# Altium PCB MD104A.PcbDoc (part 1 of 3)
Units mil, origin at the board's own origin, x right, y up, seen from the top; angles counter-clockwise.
Board outline 3684 x 4279 mil, 4 copper layers (Top Layer, GND Layer, Power Layer, Bottom Layer), stack 61.2 mil thick; 215 components, 107 nets, 500 pads, 726 vias.
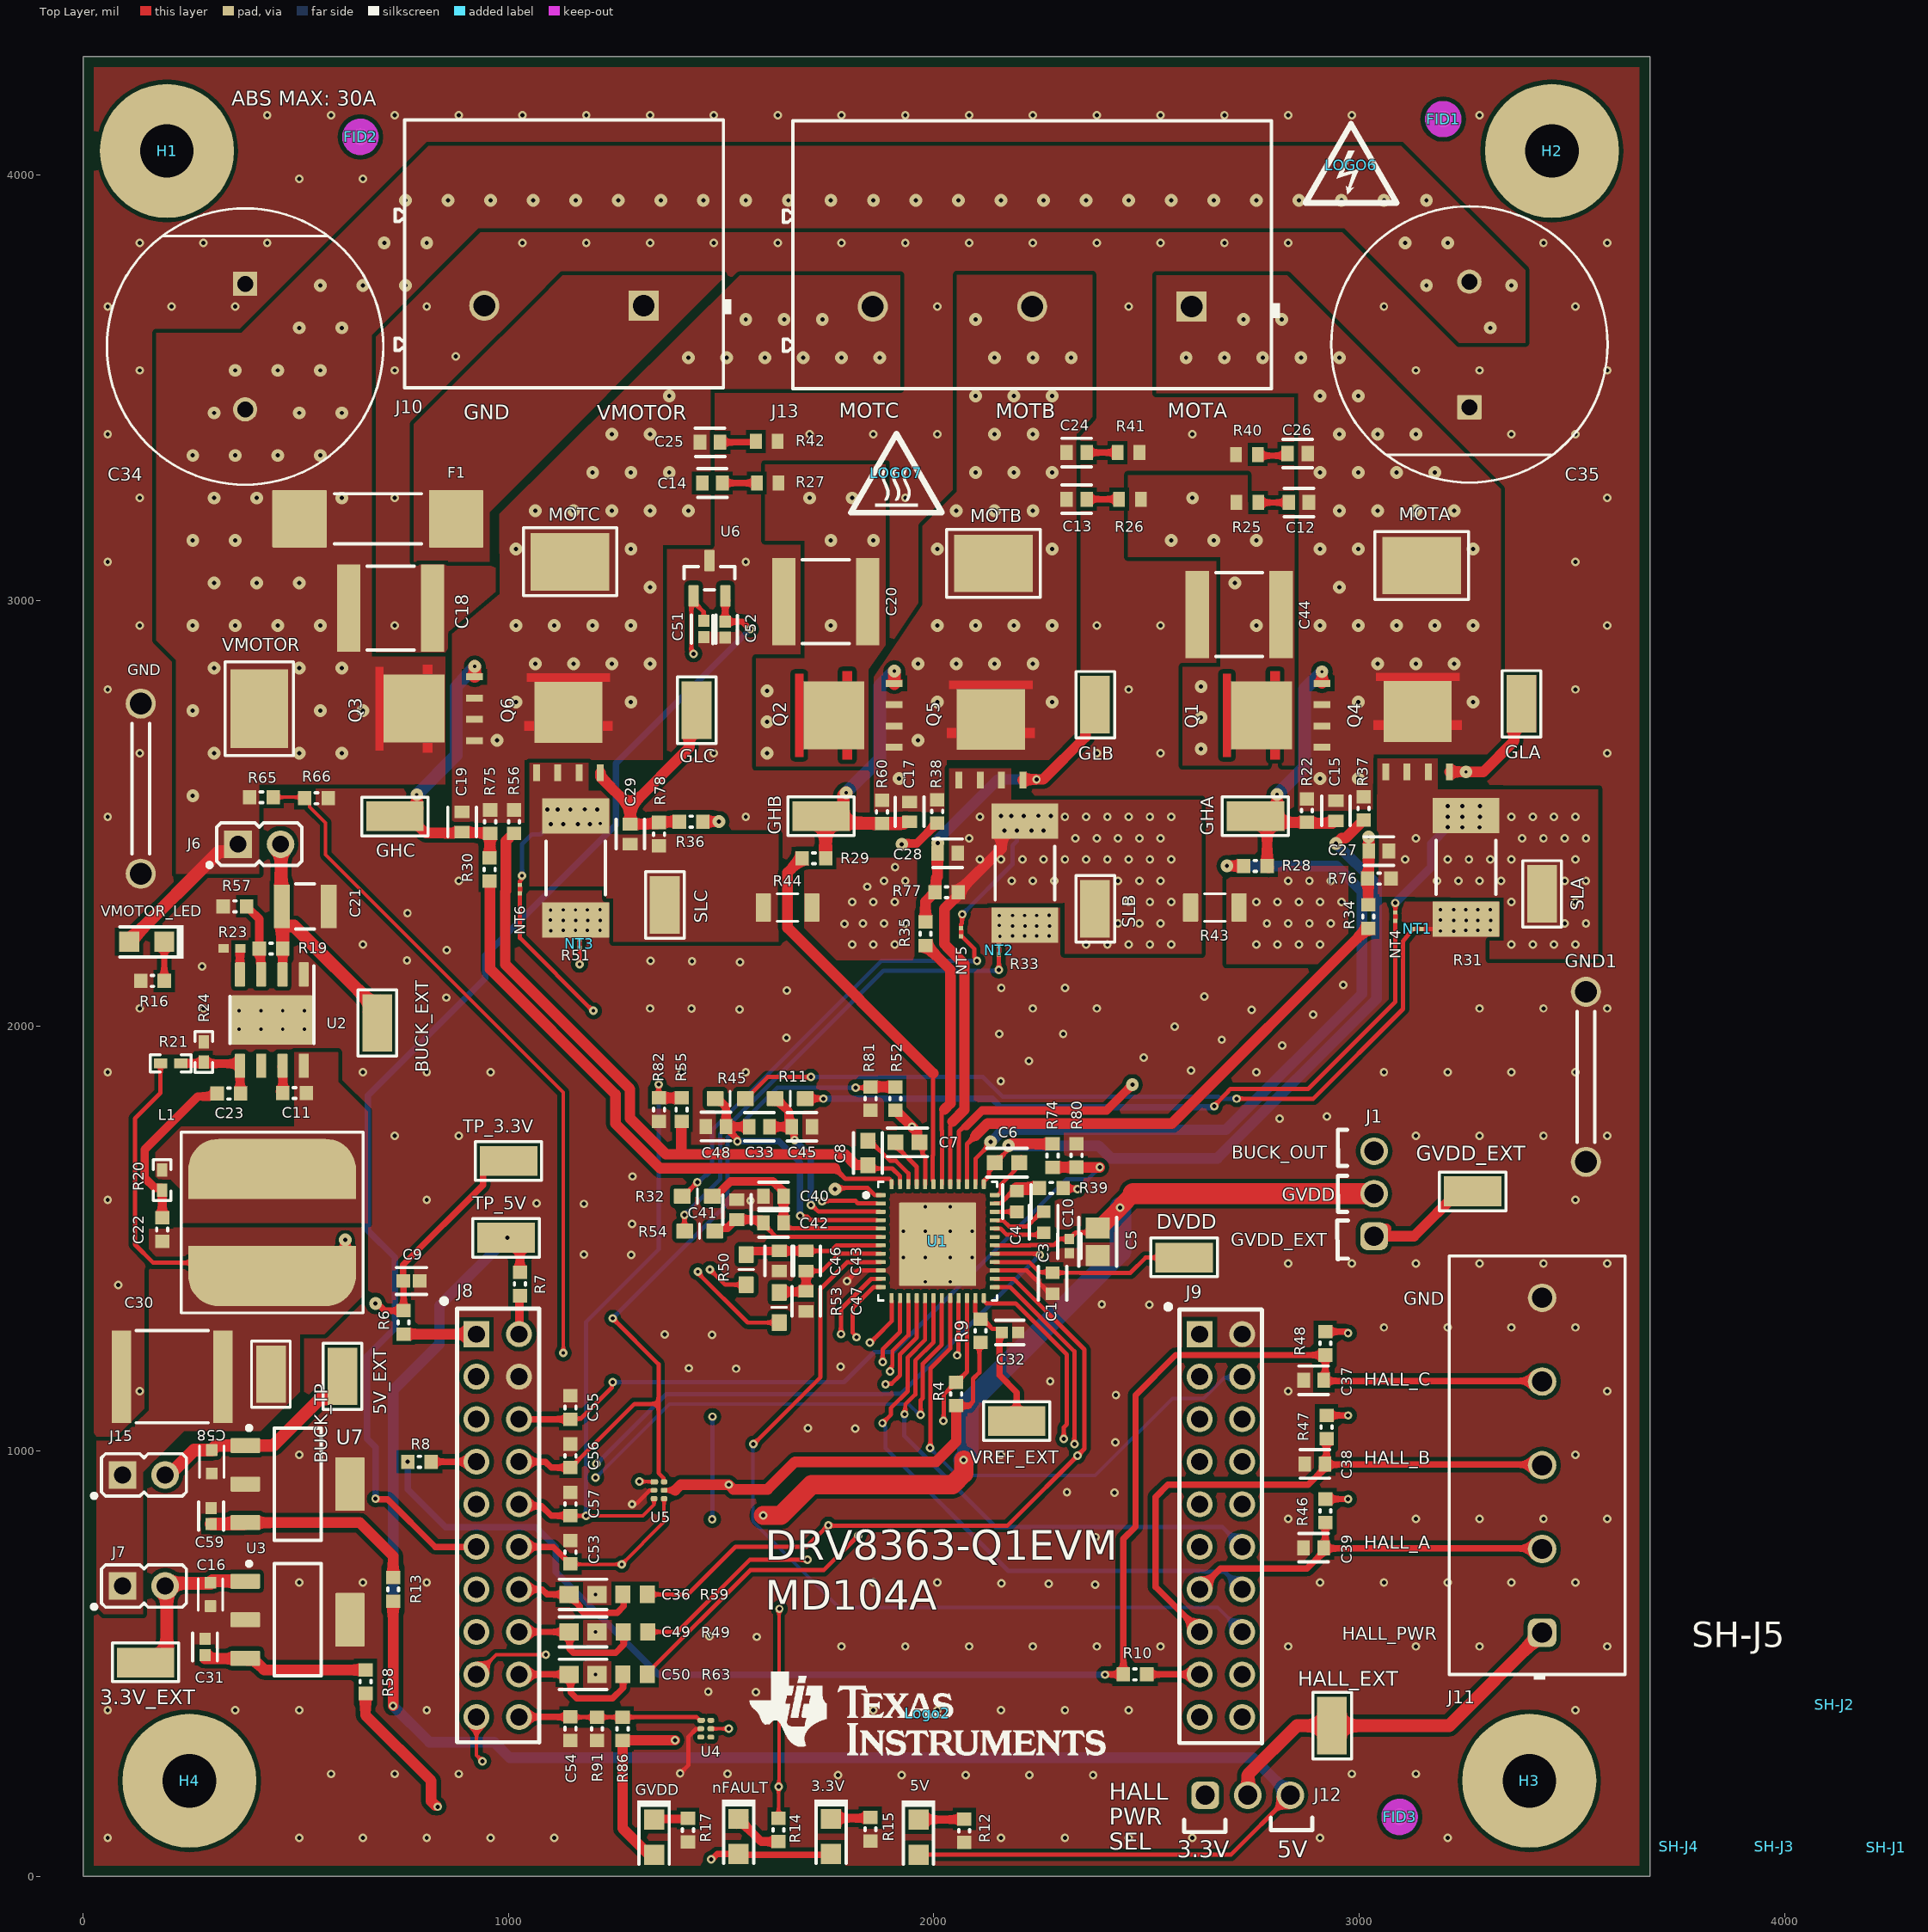
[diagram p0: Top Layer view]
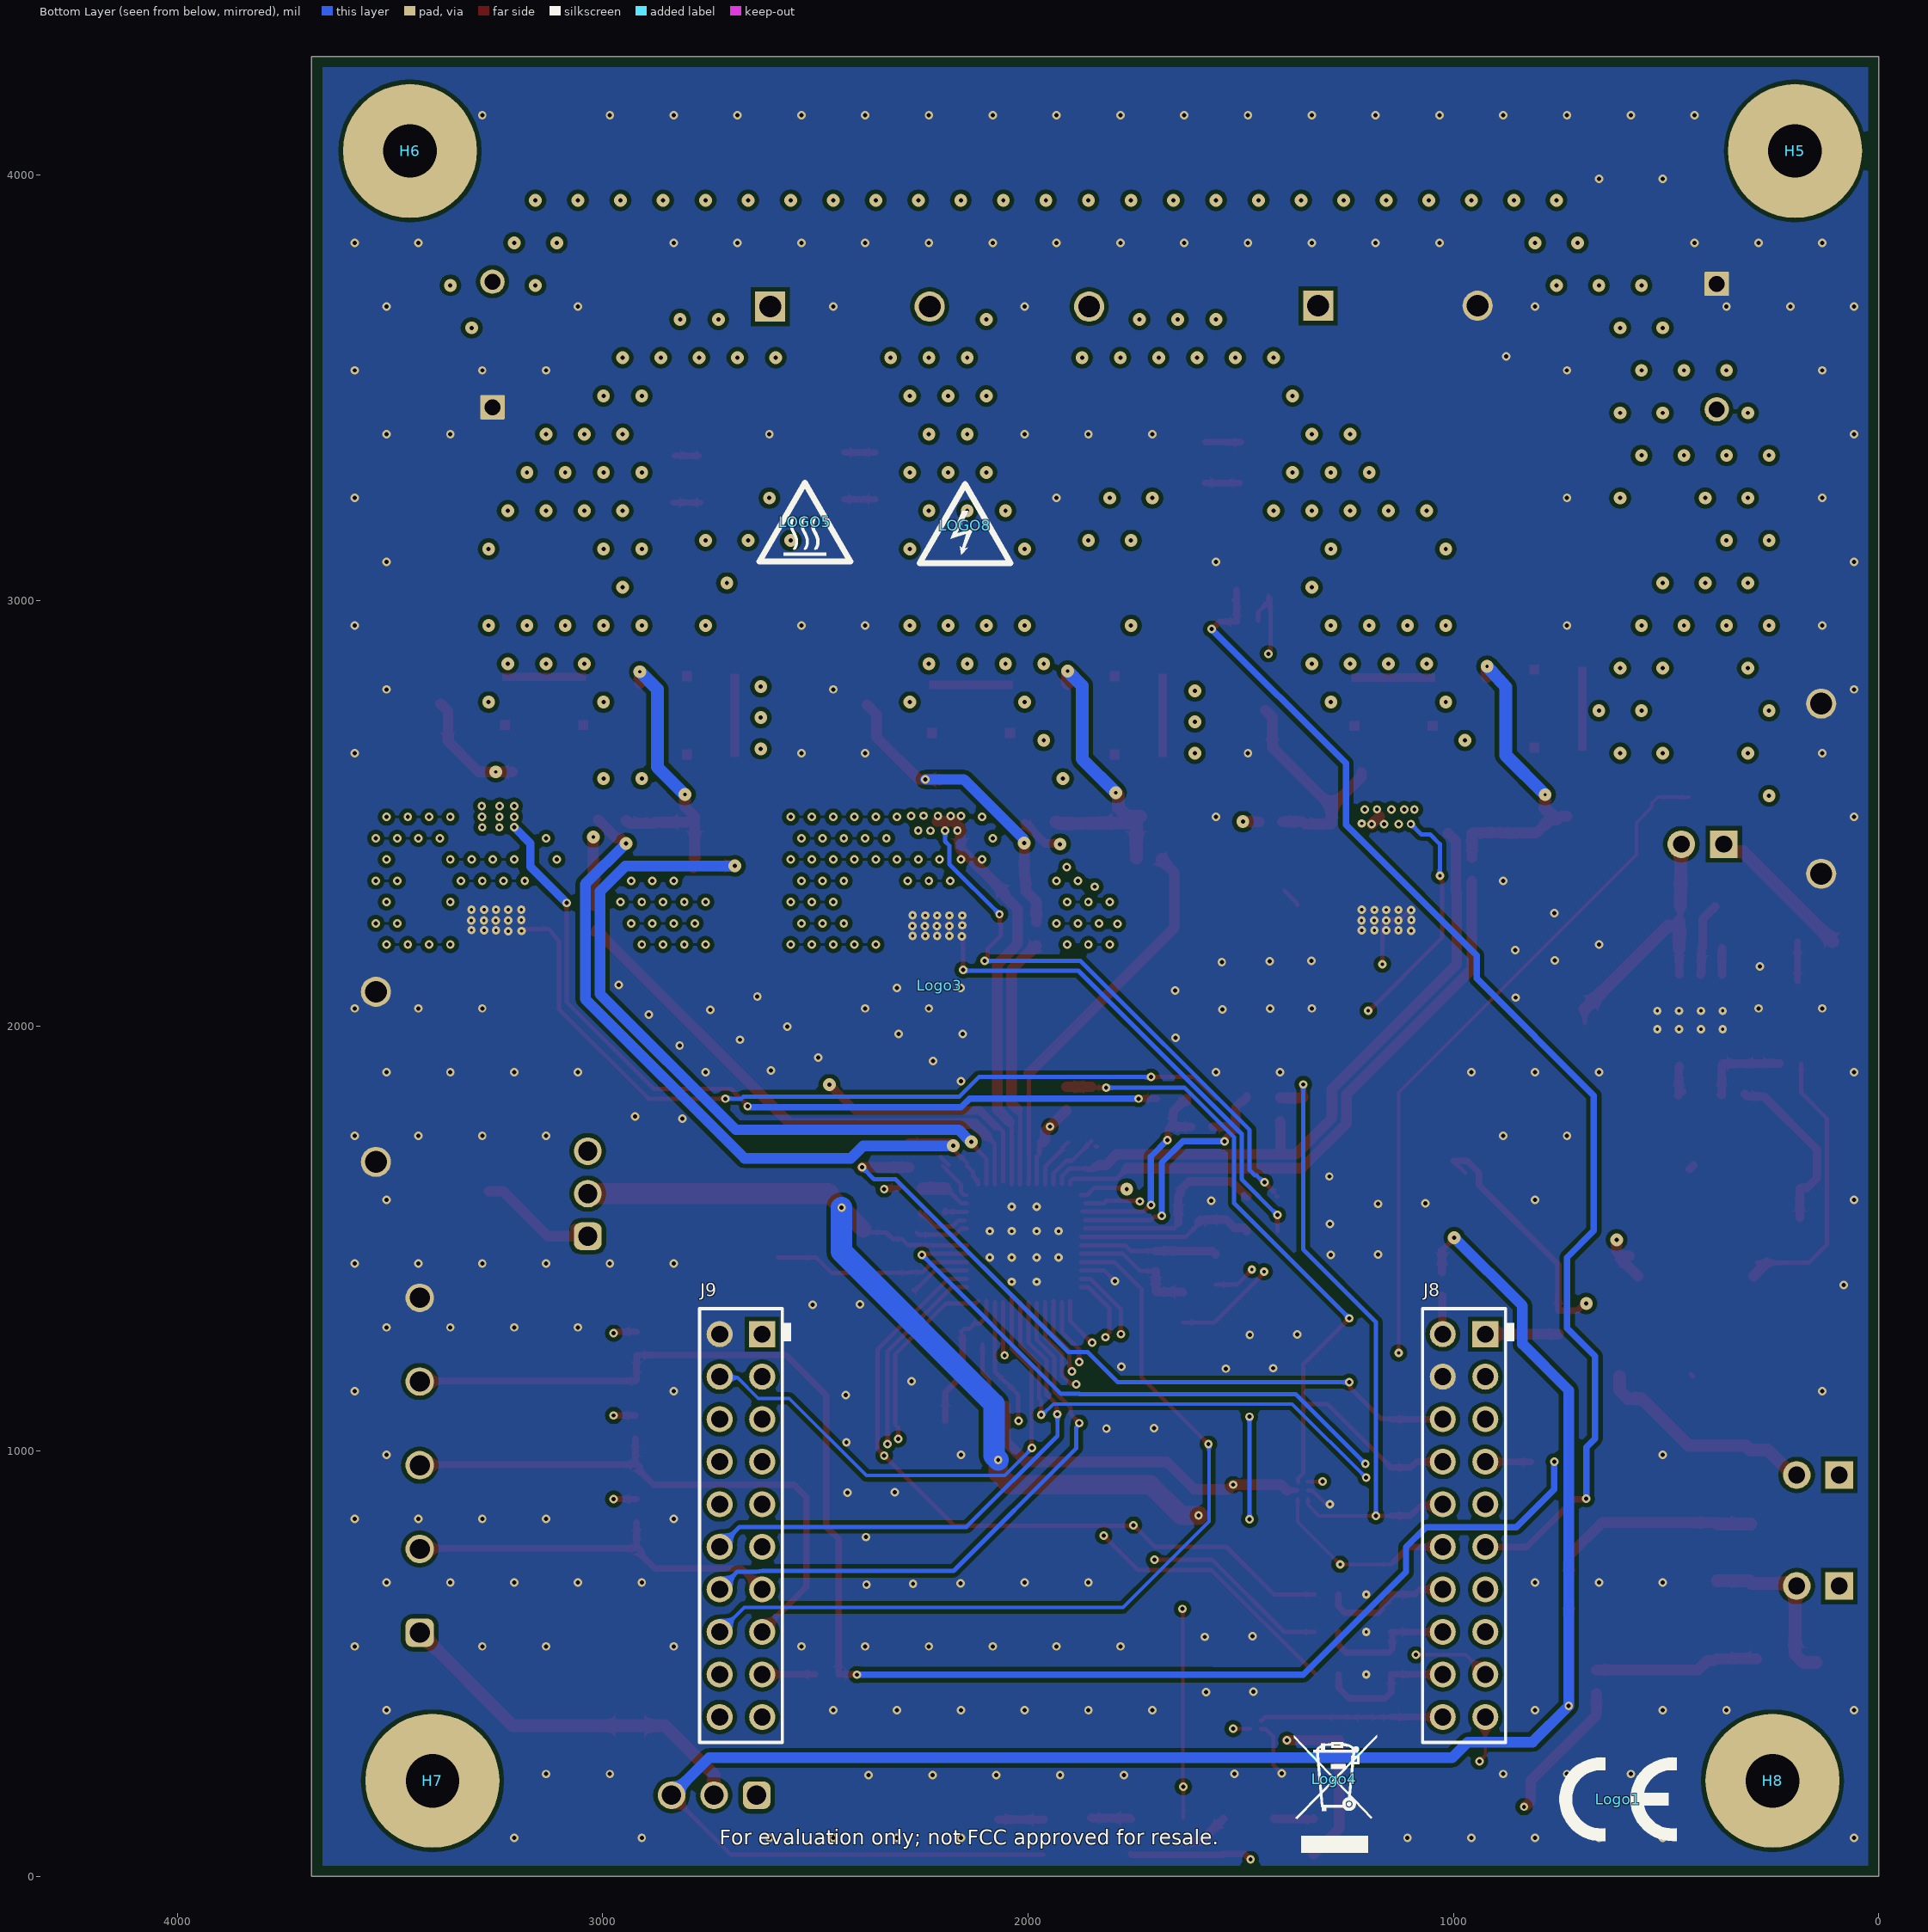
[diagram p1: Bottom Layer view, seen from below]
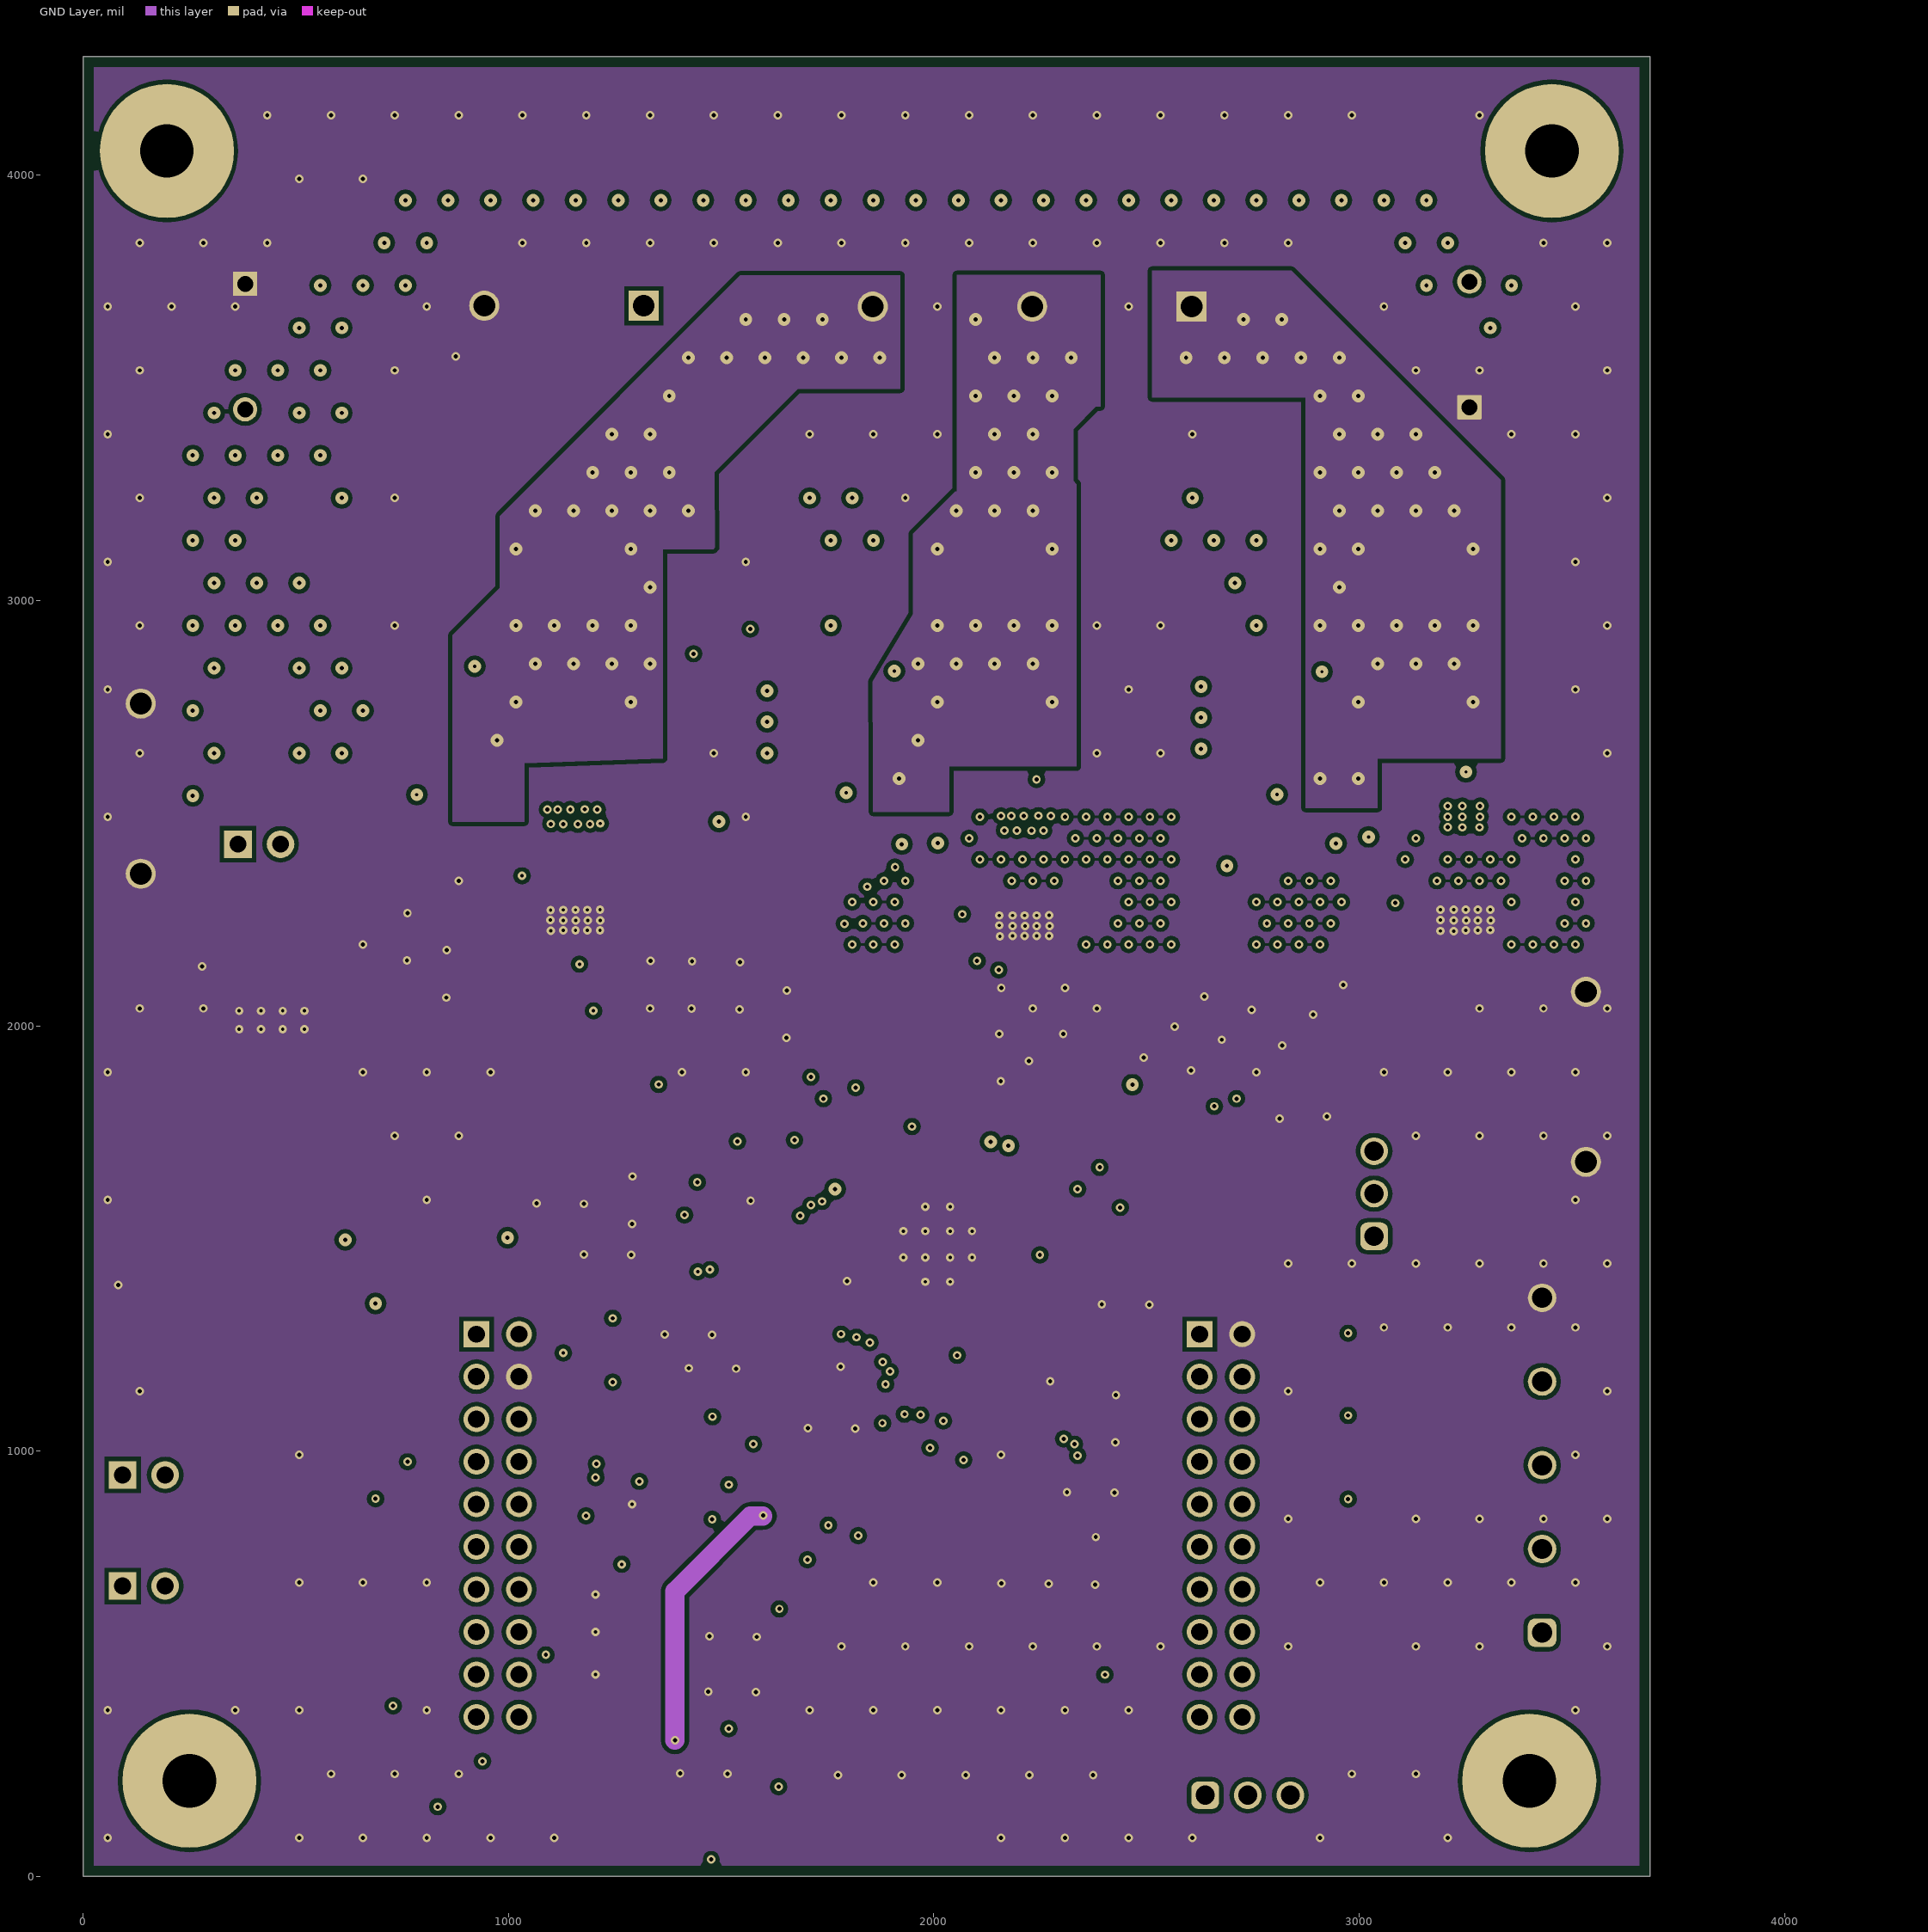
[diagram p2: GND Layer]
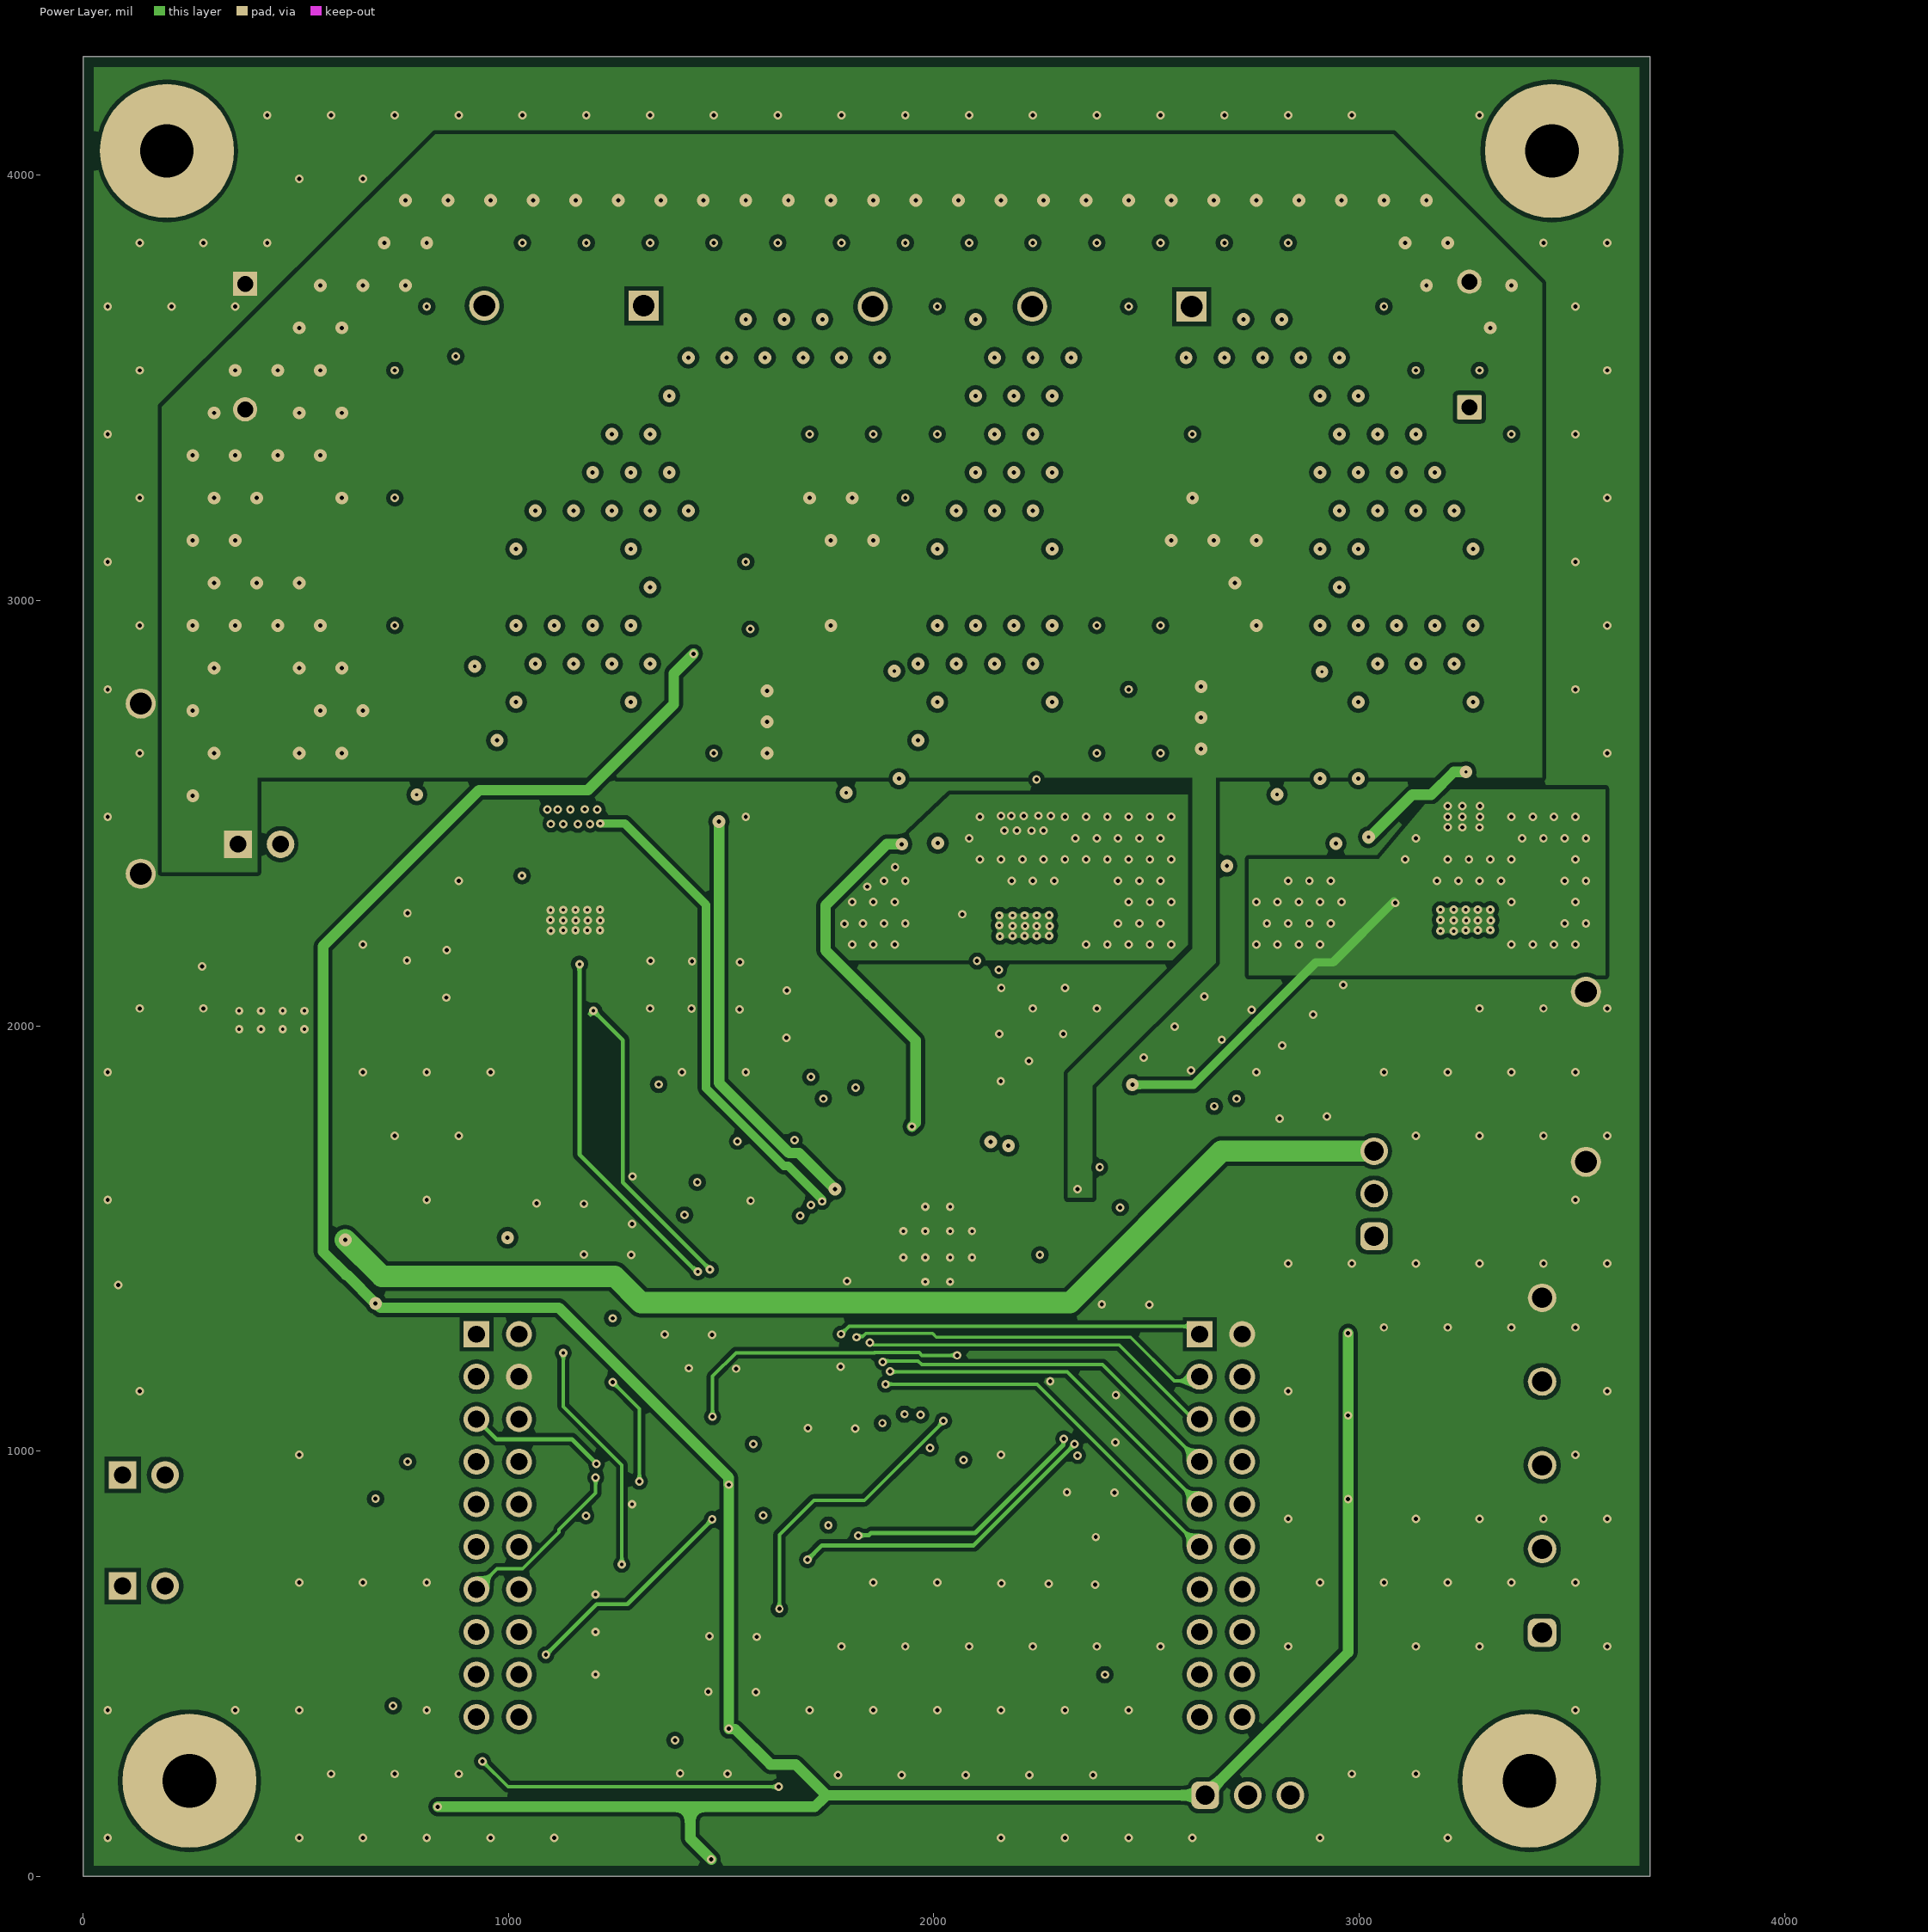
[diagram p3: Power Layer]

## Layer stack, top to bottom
Top Solder: solder mask 0.4, Solder Resist, Dk 3.5
Top Layer: signal copper 2.8
Dielectric 2: core 10, FR-4 High Tg, Dk 4.8
GND Layer: signal copper 1.4
Dielectric 1: prepreg 32.8, FR-4 High Tg, Dk 4.2
Power Layer: signal copper 1.4
Dielectric 3: core 10, FR-4 High Tg, Dk 4.8
Bottom Layer: signal copper 2.8
Solder Side: solder mask 0.4, Solder Resist, Dk 3.5

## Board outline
0,0 3684,0 3684,4279 0,4279

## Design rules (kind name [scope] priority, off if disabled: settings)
AcuteAngle [All] p1: minimum=4.50000000000000E+0001 checktracksonly=FALSE
AssemblyTestPointUsage [All] p1: valid=2
BoardOutlineClearance BoardOutlineClearance_MountingHoles [OnCopper and InComponentClass('Mounting Holes')] p1: gap=39.37 ignorepadtopadclearanceinfootprint=FALSE
BoardOutlineClearance BoardOutlineClearance_Poly [OnCopper and IsPoly] p2: gap=25 ignorepadtopadclearanceinfootprint=FALSE
BoardOutlineClearance [OnCopper and Not InComponentClass('Logo') and not InComponentClass('FiducialMark') and not InRegion(1000,500,4000,800) and not InPoly] p3: gap=50 ignorepadtopadclearanceinfootprint=FALSE
Clearance Clearance_Keepouts [((IsTrack Or IsArc) And Not InPoly) And IsFree and IsKeepOut vs ((IsTrack Or IsArc) And Not InPoly) And IsFree and IsKeepOut] p1: gap=0 ignorepadtopadclearanceinfootprint=FALSE
Clearance Clearance_Poly [InPolygon] p2: gap=10 ignorepadtopadclearanceinfootprint=TRUE
Clearance Clearance_FiducialMark [IsKeepOut and InComponentClass('FiducialMark') vs IsPad and InComponentClass('FiducialMark')] p3: gap=0 ignorepadtopadclearanceinfootprint=FALSE
Clearance [All] p4: gap=7.87 ignorepadtopadclearanceinfootprint=TRUE
ComponentClearance ComponentClearance_MountingHoles_FiducialMarks [InComponentClass('Mounting Holes') vs InComponentClass('FiducialMark')] p1: gap=50 collisioncheckmode=3 verticalgap=10 showdistances=FALSE
ComponentClearance ComponentClearance_Shunt [InComponentClass('Header') vs InComponentClass('Shunt')] p2: gap=0 collisioncheckmode=3 verticalgap=0 showdistances=FALSE
ComponentClearance ComponentClearance_Logo [InComponentClass('Logo')] p3: gap=20 collisioncheckmode=3 verticalgap=10 showdistances=FALSE
ComponentClearance ComponentClearance_ScrewToNut [(HasFootprint('NY PMS 440 0025 PH')) vs (HasFootprint('Keystone_1902C'))] p4: gap=5 collisioncheckmode=3 verticalgap=10 showdistances=FALSE
ComponentClearance ComponentClearance_MountingHoles [InComponentClass('Mounting Holes')] p5: gap=10 collisioncheckmode=3 verticalgap=100000 showdistances=FALSE
ComponentClearance ComponentClearance_SmallPassives [HasFootprint('0201*') or HasFootprint('0402*') or HasFootprint('0508') or HasFootprint('0603*') or HasFootprint('0612') or HasFootprint('0805*') or HasFootprint('0815*') or HasFootprint('0830*') or HasFootprint('1206*') or HasFootprint('1210*') or HasFootprint('1808*') or HasFootprint('1812*') or HasFootprint('1825*') or HasFootprint('2010*') or HasFootprint('2220*') or HasFootprint('2225*') or HasFootprint('2512*') or HasFootprint('2728*') or HasFootprint('3518*') vs HasFootprint('0201*') or HasFootprint('0402*') or HasFootprint('0508') or HasFootprint('0603*') or HasFootprint('0612') or HasFootprint('0805*') or HasFootprint('0815*') or HasFootprint('0830*') or HasFootprint('1206*') or HasFootprint('1210*') or HasFootprint('1808*') or HasFootprint('1812*') or HasFootprint('1825*') or HasFootprint('2010*') or HasFootprint('2220*') or HasFootprint('2225*') or HasFootprint('2512*') or HasFootprint('2728*') or HasFootprint('3518*')] p6: gap=14.96 collisioncheckmode=3 verticalgap=10 showdistances=FALSE
ComponentClearance ComponentClearance_THtoSMT [IsThruComponent vs IsSMTComponent] p7: gap=40 collisioncheckmode=3 verticalgap=30 showdistances=FALSE
ComponentClearance ComponentClearance_THtoTH [IsThruComponent vs IsThruComponent] p8: gap=30 collisioncheckmode=3 verticalgap=30 showdistances=FALSE
ComponentClearance [All] p9: gap=30 collisioncheckmode=3 verticalgap=10 showdistances=FALSE
DiffPairsRouting [All] p1: maxlimit=100 minlimit=10 mostfreqgap=10 toplayer_minwidth=15 toplayer_maxwidth=15 toplayer_prefwidth=15 midlayer1_minwidth=15 midlayer1_maxwidth=15 midlayer1_prefwidth=15 midlayer2_minwidth=15 midlayer2_maxwidth=15 midlayer2_prefwidth=15 bottomlayer_minwidth=15 bottomlayer_maxwidth=15 bottomlayer_prefwidth=15 maxuncoupledlength=1000
FabricationTestPointUsage TestPointUsage [All] p1: valid=2 allowmultiple=FALSE
FabricationTestpoint Testpoint [All] p1: side=3 testpointundercomponent=TRUE minsize=40 maxsize=100 preferedsize=60 minholesize=0 maxholesize=40 preferedholesize=32 testpointgrid=1 allowsidetop=TRUE allowsidebottom=TRUE usegrid=TRUE gridtolerance=0.01
FanoutControl Fanout_LCC [IsLCC] p1: bgadir=Out bgaviamode=Centered fanoutstyle=Auto fanoutdirection=Alternating viagrid=1 // Fanout_LCC (Default Rule)
FanoutControl Fanout_BGA [IsBGA] p2: bgadir=Out bgaviamode=Centered fanoutstyle=Auto fanoutdirection=Alternating viagrid=1 // Fanout_BGA (Default Rule)
FanoutControl Fanout_Default [All] p4: bgadir=Out bgaviamode=Centered fanoutstyle=Auto fanoutdirection=Alternating viagrid=1 // Fanout_Default (Default Rule)
FanoutControl Fanout_Small [(CompPinCount < 5)] p5: bgadir=Out bgaviamode=Centered fanoutstyle=Auto fanoutdirection=OutThenIn viagrid=1 // Fanout_Small (Default Rule)
Height [All] p1 off: minheight=0 maxheight=1000 prefheight=500
HoleSize [All] p1: absolutevalues=TRUE maxlimit=250 minlimit=7.8 maxpercent=80.000 minpercent=20.000
MinimumAnnularRing MinimumAnnularRing_ThermalPadVias [IsVia and InAnyComponent] p1: minimumring=5
MinimumAnnularRing [All] p2: minimumring=5
MinimumSolderMaskSliver MinimumSolderMaskSliver_Logo [InComponentClass('Logo') vs InComponentClass('Logo')] p1: minsoldermaskwidth=0.7
MinimumSolderMaskSliver [All] p2: minsoldermaskwidth=3.94
PlaneConnect [All] p1: planeconnectstyle=Direct reliefexpansion=10 reliefentries=4 reliefconductorwidth=10 reliefairgap=10
PolygonConnect PolygonConnect_57 [All] p1: connectstyle=Direct reliefconductorwidth=10 reliefentries=4 polygonreliefangle="90 Angle" airgapwidth=10
PolygonConnect PolygonConnect_56 [All vs IsNamedPolygon('Top Layer-MOTB')] p2: connectstyle=Direct reliefconductorwidth=10 reliefentries=4 polygonreliefangle="90 Angle" airgapwidth=10
PolygonConnect PolygonConnect_55 [All vs IsNamedPolygon('TOP_LAYER_SLB_P107')] p3: connectstyle=Direct reliefconductorwidth=10 reliefentries=4 polygonreliefangle="90 Angle" airgapwidth=10
PolygonConnect PolygonConnect_54 [All vs IsNamedPolygon('TOP_LAYER_SLC_P118')] p4: connectstyle=Direct reliefconductorwidth=10 reliefentries=4 polygonreliefangle="90 Angle" airgapwidth=10
PolygonConnect PolygonConnect_53 [All vs IsNamedPolygon('TOP_LAYER_SLC_P118')] p5: connectstyle=Direct reliefconductorwidth=10 reliefentries=4 polygonreliefangle="90 Angle" airgapwidth=10
PolygonConnect PolygonConnect_52 [All vs IsNamedPolygon('TOP_LAYER_SLB_P113')] p6: connectstyle=Direct reliefconductorwidth=10 reliefentries=4 polygonreliefangle="90 Angle" airgapwidth=10
PolygonConnect [All vs IsNamedPolygon('TOP_LAYER_SLA_P109')] p7: connectstyle=Direct reliefconductorwidth=10 reliefentries=4 polygonreliefangle="90 Angle" airgapwidth=10
PolygonConnect PolygonConnect_51 [All vs IsNamedPolygon('TOP_LAYER_NONET_P084')] p8: connectstyle=Direct reliefconductorwidth=10 reliefentries=4 polygonreliefangle="90 Angle" airgapwidth=10
PolygonConnect PolygonConnect_50 [All vs IsNamedPolygon('BOTTOM_LAYER_GND_P082')] p9: connectstyle=Direct reliefconductorwidth=10 reliefentries=4 polygonreliefangle="90 Angle" airgapwidth=10
PolygonConnect PolygonConnect_49 [All vs IsNamedPolygon('GND_LAYER_LSS_P072')] p10: connectstyle=Direct reliefconductorwidth=10 reliefentries=4 polygonreliefangle="90 Angle" airgapwidth=10
PolygonConnect PolygonConnect_48 [All vs IsNamedPolygon('POWER_LAYER_LSS_P076')] p11: connectstyle=Direct reliefconductorwidth=10 reliefentries=4 polygonreliefangle="90 Angle" airgapwidth=10
PolygonConnect PolygonConnect_47 [All vs IsNamedPolygon('GND_LAYER_LSS_P072')] p12: connectstyle=Direct reliefconductorwidth=10 reliefentries=4 polygonreliefangle="90 Angle" airgapwidth=10
PolygonConnect PolygonConnect_46 [All vs IsNamedPolygon('BOTTOM_LAYER_GND_P076')] p13: connectstyle=Direct reliefconductorwidth=10 reliefentries=4 polygonreliefangle="90 Angle" airgapwidth=10
PolygonConnect PolygonConnect_45 [All vs IsNamedPolygon('BOTTOM_LAYER_OUTA_P076')] p14: connectstyle=Direct reliefconductorwidth=10 reliefentries=4 polygonreliefangle="90 Angle" airgapwidth=10
PolygonConnect PolygonConnect_44 [All vs IsNamedPolygon('BOTTOM_LAYER_OUTB_P074')] p15: connectstyle=Direct reliefconductorwidth=10 reliefentries=4 polygonreliefangle="90 Angle" airgapwidth=10
PolygonConnect PolygonConnect_43 [All vs IsNamedPolygon('BOTTOM_LAYER_OUTC_P072')] p16: connectstyle=Direct reliefconductorwidth=10 reliefentries=4 polygonreliefangle="90 Angle" airgapwidth=10
PolygonConnect PolygonConnect_42 [All vs IsNamedPolygon('BOTTOM_LAYER_NONET_P070')] p17: connectstyle=Direct reliefconductorwidth=10 reliefentries=4 polygonreliefangle="90 Angle" airgapwidth=10
PolygonConnect PolygonConnect_41 [All vs IsNamedPolygon('POWER_LAYER_GND_P068')] p18: connectstyle=Direct reliefconductorwidth=10 reliefentries=4 polygonreliefangle="90 Angle" airgapwidth=10
PolygonConnect PolygonConnect_40 [All vs IsNamedPolygon('GND_LAYER_GND_P066')] p19: connectstyle=Direct reliefconductorwidth=10 reliefentries=4 polygonreliefangle="90 Angle" airgapwidth=10
PolygonConnect PolygonConnect_39 [All vs IsNamedPolygon('TOP_LAYER_GND_P070')] p20: connectstyle=Direct reliefconductorwidth=10 reliefentries=4 polygonreliefangle="90 Angle" airgapwidth=10
PolygonConnect PolygonConnect_38 [All vs IsNamedPolygon('BOTTOM_LAYER_GND')] p21: connectstyle=Direct reliefconductorwidth=10 reliefentries=4 polygonreliefangle="90 Angle" airgapwidth=10
PolygonConnect PolygonConnect_37 [All vs IsNamedPolygon('BOTTOM_LAYER_GND')] p22: connectstyle=Direct reliefconductorwidth=10 reliefentries=4 polygonreliefangle="90 Angle" airgapwidth=10
PolygonConnect PolygonConnect_36 [All vs IsNamedPolygon('GND_LAYER_OUTA_P060')] p23: connectstyle=Direct reliefconductorwidth=10 reliefentries=4 polygonreliefangle="90 Angle" airgapwidth=10
PolygonConnect PolygonConnect_35 [All vs IsNamedPolygon('GND_LAYER_OUTB_P058')] p24: connectstyle=Direct reliefconductorwidth=10 reliefentries=4 polygonreliefangle="90 Angle" airgapwidth=10
PolygonConnect PolygonConnect_34 [All vs IsNamedPolygon('GND_LAYER_OUTC_P056')] p25: connectstyle=Direct reliefconductorwidth=10 reliefentries=4 polygonreliefangle="90 Angle" airgapwidth=10
PolygonConnect PolygonConnect_33 [All vs IsNamedPolygon('POWER_LAYER_PVDD_P052')] p26: connectstyle=Direct reliefconductorwidth=10 reliefentries=4 polygonreliefangle="90 Angle" airgapwidth=10
PolygonConnect PolygonConnect_32 [All vs IsNamedPolygon('POWER_LAYER_PVDD_P052')] p27: connectstyle=Direct reliefconductorwidth=10 reliefentries=4 polygonreliefangle="90 Angle" airgapwidth=10
PolygonConnect PolygonConnect_31 [All vs IsNamedPolygon('POWER_LAYER_OUTA_P050')] p28: connectstyle=Direct reliefconductorwidth=10 reliefentries=4 polygonreliefangle="90 Angle" airgapwidth=10
PolygonConnect PolygonConnect_30 [All vs IsNamedPolygon('POWER_LAYER_OUTB_P048')] p29: connectstyle=Direct reliefconductorwidth=10 reliefentries=4 polygonreliefangle="90 Angle" airgapwidth=10
PolygonConnect PolygonConnect_29 [All vs IsNamedPolygon('POWER_LAYER_OUTC_P046')] p30: connectstyle=Direct reliefconductorwidth=10 reliefentries=4 polygonreliefangle="90 Angle" airgapwidth=10
PolygonConnect PolygonConnect_28 [All vs IsNamedPolygon('POWER_LAYER_AVDD_P062')] p31: connectstyle=Direct reliefconductorwidth=10 reliefentries=4 polygonreliefangle="90 Angle" airgapwidth=10
PolygonConnect PolygonConnect_27 [All vs IsNamedPolygon('SIGNAL_LAYER_1_OUTA_P060')] p32: connectstyle=Direct reliefconductorwidth=10 reliefentries=4 polygonreliefangle="90 Angle" airgapwidth=10
PolygonConnect PolygonConnect_26 [All vs IsNamedPolygon('SIGNAL_LAYER_1_OUTB_P058')] p33: connectstyle=Direct reliefconductorwidth=10 reliefentries=4 polygonreliefangle="90 Angle" airgapwidth=10
PolygonConnect PolygonConnect_25 [All vs IsNamedPolygon('SIGNAL_LAYER_1_OUTC_P056')] p34: connectstyle=Direct reliefconductorwidth=10 reliefentries=4 polygonreliefangle="90 Angle" airgapwidth=10
PolygonConnect PolygonConnect_24 [All vs IsNamedPolygon('SIGNAL_LAYER_2_PVDD_P054')] p35: connectstyle=Direct reliefconductorwidth=10 reliefentries=4 polygonreliefangle="90 Angle" airgapwidth=10
PolygonConnect PolygonConnect_23 [All vs IsNamedPolygon('SIGNAL_LAYER_2_PVDD_P052')] p36: connectstyle=Direct reliefconductorwidth=10 reliefentries=4 polygonreliefangle="90 Angle" airgapwidth=10
PolygonConnect PolygonConnect_22 [All vs IsNamedPolygon('SIGNAL_LAYER_2_OUTA_P050')] p37: connectstyle=Direct reliefconductorwidth=10 reliefentries=4 polygonreliefangle="90 Angle" airgapwidth=10
PolygonConnect PolygonConnect_21 [All vs IsNamedPolygon('SIGNAL_LAYER_2_OUTB_P048')] p38: connectstyle=Direct reliefconductorwidth=10 reliefentries=4 polygonreliefangle="90 Angle" airgapwidth=10
PolygonConnect PolygonConnect_20 [All vs IsNamedPolygon('SIGNAL_LAYER_2_OUTC_P046')] p39: connectstyle=Direct reliefconductorwidth=10 reliefentries=4 polygonreliefangle="90 Angle" airgapwidth=10
PolygonConnect PolygonConnect_19 [All vs IsNamedPolygon('TOP_LAYER_AVDD_P044')] p40: connectstyle=Direct reliefconductorwidth=10 reliefentries=4 polygonreliefangle="90 Angle" airgapwidth=10
PolygonConnect PolygonConnect_18 [All vs IsNamedPolygon('TOP_LAYER_PVDD_P034')] p41: connectstyle=Direct reliefconductorwidth=10 reliefentries=4 polygonreliefangle="90 Angle" airgapwidth=10
PolygonConnect PolygonConnect_17 [All vs IsNamedPolygon('SIGNAL_LAYER_1_OUTC_P036')] p42: connectstyle=Direct reliefconductorwidth=10 reliefentries=4 polygonreliefangle="90 Angle" airgapwidth=10
PolygonConnect PolygonConnect_16 [All vs IsNamedPolygon('TOP_LAYER_PVDD_P034')] p43: connectstyle=Direct reliefconductorwidth=10 reliefentries=4 polygonreliefangle="90 Angle" airgapwidth=10
PolygonConnect PolygonConnect_15 [All vs IsNamedPolygon('TOP_LAYER_LSS_P030')] p44: connectstyle=Direct reliefconductorwidth=10 reliefentries=4 polygonreliefangle="90 Angle" airgapwidth=10
PolygonConnect PolygonConnect_14 [All vs IsNamedPolygon('TOP_LAYER_GLC_FET_P024')] p45: connectstyle=Direct reliefconductorwidth=10 reliefentries=4 polygonreliefangle="90 Angle" airgapwidth=10
PolygonConnect PolygonConnect_13 [All vs IsNamedPolygon('TOP_LAYER_GLB_FET_P026')] p46: connectstyle=Direct reliefconductorwidth=10 reliefentries=4 polygonreliefangle="90 Angle" airgapwidth=10
PolygonConnect PolygonConnect_12 [All vs IsNamedPolygon('TOP_LAYER_GLA_FET_P028')] p47: connectstyle=Direct reliefconductorwidth=10 reliefentries=4 polygonreliefangle="90 Angle" airgapwidth=10
PolygonConnect PolygonConnect_11 [All vs IsNamedPolygon('TOP_LAYER_GHB_FET_P020')] p48: connectstyle=Direct reliefconductorwidth=10 reliefentries=4 polygonreliefangle="90 Angle" airgapwidth=10
PolygonConnect PolygonConnect_10 [All vs IsNamedPolygon('TOP_LAYER_GHA_FET_P022')] p49: connectstyle=Direct reliefconductorwidth=10 reliefentries=4 polygonreliefangle="90 Angle" airgapwidth=10
PolygonConnect PolygonConnect_9 [All vs IsNamedPolygon('TOP_LAYER_GHC_FET_P018')] p50: connectstyle=Direct reliefconductorwidth=10 reliefentries=4 polygonreliefangle="90 Angle" airgapwidth=10
PolygonConnect PolygonConnect_8 [All vs IsNamedPolygon('TOP_LAYER_GND_P014')] p51: connectstyle=Direct reliefconductorwidth=10 reliefentries=4 polygonreliefangle="90 Angle" airgapwidth=10
PolygonConnect PolygonConnect_7 [All vs IsNamedPolygon('TOP_LAYER_GND_P014')] p52: connectstyle=Direct reliefconductorwidth=10 reliefentries=4 polygonreliefangle="90 Angle" airgapwidth=10
PolygonConnect PolygonConnect_6 [All vs IsNamedPolygon('TOP_LAYER_PVDD_P008')] p53: connectstyle=Direct reliefconductorwidth=10 reliefentries=4 polygonreliefangle="90 Angle" airgapwidth=10
PolygonConnect PolygonConnect_5 [All vs IsNamedPolygon('TOP_LAYER_PVDD_P008')] p54: connectstyle=Direct reliefconductorwidth=10 reliefentries=4 polygonreliefangle="90 Angle" airgapwidth=10
PolygonConnect PolygonConnect_4 [All vs IsNamedPolygon('TOP_LAYER_PVDD_P008')] p55: connectstyle=Direct reliefconductorwidth=10 reliefentries=4 polygonreliefangle="90 Angle" airgapwidth=10
PolygonConnect PolygonConnect_3 [All vs IsNamedPolygon('TOP_LAYER_OUTA_P006')] p56: connectstyle=Direct reliefconductorwidth=10 reliefentries=4 polygonreliefangle="90 Angle" airgapwidth=10
PolygonConnect PolygonConnect_2 [All vs IsNamedPolygon('TOP_LAYER_OUTB_P004')] p57: connectstyle=Direct reliefconductorwidth=10 reliefentries=4 polygonreliefangle="90 Angle" airgapwidth=10
PolygonConnect PolygonConnect_1 [All vs IsNamedPolygon('TOP_LAYER_OUTC_P002')] p58: connectstyle=Direct reliefconductorwidth=10 reliefentries=4 polygonreliefangle="90 Angle" airgapwidth=10
RoutingVias ThermalPadVias [IsVia and InAnyComponent] p1 off: holewidth=7.87 width=19.68 viastyle="Through Hole" minholewidth=7.87 minwidth=19.68 maxholewidth=12.99 maxwidth=23.62
RoutingVias [All] p2 off: holewidth=10 width=20 viastyle="Through Hole" minholewidth=10 minwidth=20 maxholewidth=10 maxwidth=20
SilkToBoardRegionClearance [Not ((IsComment or IsDesignator) And (Hide <> 'False')) and not InRegion(1000,500,4000,800)] p1:
SilkToSilkClearance SilkToSilkClearance_Pb-FreeLogo [(HasFootprint('Pb-Free_Overlay_Medium') OR HasFootprint('Pb-Free_Overlay_Small')) vs (HasFootprint('Pb-Free_Overlay_Medium') OR HasFootprint('Pb-Free_Overlay_Small'))] p1: silktosilkclearance=0
SilkToSilkClearance [All] p2: silktosilkclearance=1
SilkToSolderMaskClearance SilkToComponentPadClearance [(IsPad or IsFill or IsRegion) and InAnycomponent] p1: minsilkscreentomaskgap=2 clearancetoexposedcopper=TRUE
SilkToSolderMaskClearance "Silk to Solder Mask Opening" [All] p2: minsilkscreentomaskgap=3.94 clearancetoexposedcopper=FALSE
SolderMaskExpansion [All] p1: expansion=1.97 istentingtop=FALSE
UnRoutedNet [All] p1: checkbadconnections=TRUE
Width [All] p1: maxlimit=100 minlimit=6 preferedwidth=10 checkconnectedcopper=TRUE
13 further rules are at their usual default settings.

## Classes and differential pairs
component class "Mounting Holes": H5 H6 H7 H8
component class MD104_Power: 3.3V 3.3V_EXT 5V 5V_EXT BUCK_EXT BUCK_TP C11 C16 C21 C22 C23 C30 C31 C37 C38 C39 C58 C59 F1 GND GND1 GVDD HALL_EXT J6 J7 J10 J11 J12 J15 L1 nFAULT R12 R13 R14 R15 R16 R17 R19 R20 R21 R23 R24 R46 R47 R48 R57 R58 SH-J2 SH-J3 SH-J4 SH-J5 U2 U3 U4 U5 U7 VMOTOR_LED
component class Shunt: SH-J1 SH-J2 SH-J3 SH-J4 SH-J5
component class MD104_SenseFeedback: C36 C49 C50 C51 C52 C53 C54 C55 C56 C57 GND3 R49 R52 R55 R59 R63 R65 R66 R74 R80 R81 R82 R86 R91 U6
component class MD104_HalfBridges: 0.635mm C12 C13 C14 C15 C17 C18 C19 C20 C24 C25 C26 C27 C28 C29 C33 C34 C35 C40 C41 C42 C43 C44 C45 C46 C47 C48 GHA GHB GHC GLA GLB GLC J13 MOTA MOTB MOTC NT1 NT2 NT3 NT4 NT6 Q1 Q2 Q3 Q4 Q5 Q6 R11 R22 R25 R26 R27 R28 R29 R30 R31 R32 R33 R34 R35 R36 R37 R38 R39 R40 R41 R42 R43 R44 R45 R50 R51 R53 R54 R56 R60 R75 R76 R77 R78 SLA SLB SLC VMOTOR
component class MD104_Driver: C1 C3 C4 C5 C6 C7 C8 C9 C10 C32 DVDD GVDD_EXT J1 J8 J9 R4 R6 R7 R8 R9 R10 SH-J1 TP_3.3V TP_5V U1 VREF_EXT
component class Header: J1 J6 J7 J12 J15
component class Logo: Logo2
component class MD104Hardware: FID1 FID2 FID3 H1 H2 H3 H4 H5 H6 H7 H8 Logo1 Logo2 Logo3 Logo4 LOGO5 LOGO6 LOGO7 LOGO8 ZZ1 ZZ2 ZZ3 ZZ4
component class FiducialMark: FID1 FID2 FID3
component class AssemblyNote: ZZ1 ZZ2 ZZ3 ZZ4

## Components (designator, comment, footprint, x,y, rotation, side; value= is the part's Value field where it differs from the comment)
3.3V "" LED_LTST-C171 1758.43,93.88 r90 top value=Green
3.3V_EXT "5015" Testpoint_Keystone_Miniature 147,502.88 r180 top
5V "" LED_LTST-C171 1963.94,92.37 r90 top
5V_EXT "5015" Testpoint_Keystone_Miniature 609.61,1175.76 r90 top
BUCK_EXT "5015" Testpoint_Keystone_Miniature 691.44,2006.47 r90 top
BUCK_TP "5015" Testpoint_Keystone_Miniature 442.04,1180.76 r270 top
C1 "1uF" FP-GRT188-0_1-e0_2_0_5-IPC_C 2278.95,1394.62 r270 top
C3 "1uF" FP-GRT188-0_1-e0_2_0_5-IPC_C 2258.39,1538.14 r270 top
C4 "1uF" FP-GRT188-0_1-e0_2_0_5-IPC_C 2195,1586.88 r270 top
C5 "10uF" FP-GRT21B-0_2-IPC_B 2385.27,1491.92 r270 top
C6 "1uF" FP-GRT188-0_1-e0_2_0_5-IPC_B 2172,1677.88 r180 top
C7 "1uF" FP-GRT188-0_1-e0_2_0_5-IPC_B 1938,1725.88 r0 top
C8 "1uF" FP-GRT188-0_1-e0_2_0_5-IPC_B 1845,1700.88 r270 top
C9 "GRT155R61C225KE13J" FP-GRT155-0_2-IPC_A 772,1399.88 r0 top
C10 "GCM155R71E104KE02D" FP-GCM155-0_05-IPC_B 2318.6,1481.96 r270 top
C11 "CGA3E2X7R2A222K080AA" 0603L 497,1841.88 r0 top value=2200pF
C12 "C0603C222K1RACAUTO" FP-C0603C-CF-MFG 2857.87,3230.15 r0 top value="2,200 pF"
C13 "C0603C222K1RACAUTO" FP-C0603C-CF-MFG 2335.55,3238.06 r180 top value="2,200 pF"
C14 "C0603C222K1RACAUTO" FP-C0603C-CF-MFG 1479.34,3276.09 r180 top value="2,200 pF"
C15 "C0603C222K1RACAUTO" FP-C0603C-CF-MFG 2945.22,2505.2 r90 top value="2,200 pF"
C16 "CGA3E3X7R1E334K080AB" FP-CGA3E3X7R1E334K080AB_0603-MFG 299.57,662.94 r90 top value=330nF
C17 "C0603C222K1RACAUTO" FP-C0603C-CF-MFG 1943,2502.88 r90 top value="2,200 pF"
C18 "CGA9N3X7S2A106K230KE" 2220_280L 723,2981.88 r0 top value=10uF
C19 "C0603C222K1RACAUTO" FP-C0603C-CF-MFG 891,2478.88 r90 top value="2,200 pF"
C20 "CGA9N3X7S2A106K230KE" 2220_280L 1746,2996.88 r180 top value=10uF
C21 "C1210C225K1RACAUTO" FP-C1210C225K1RACAUTO-MFG 521.98,2280.41 r0 top
C22 "CGA3E2X7R2A222K080AA" 0603L 186,1520.89 r90 top value=2200pF
C23 "C0603C560J1RACAUTO" 0603L 342.82,1840.41 r0 top value=56pF
C24 "C0603C222K1RACAUTO" FP-C0603C-CF-MFG 2335.55,3347.68 r0 top value="2,200 pF"
C25 "C0603C222K1RACAUTO" FP-C0603C-CF-MFG 1473.98,3371.78 r0 top value="2,200 pF"
C26 "C0603C222K1RACAUTO" FP-C0603C-CF-MFG 2855.39,3345.34 r180 top value="2,200 pF"
C27 "C0603C222K1RACAUTO" FP-C0603C-CF-MFG 3046,2410.88 r0 top value="2,200 pF"
C28 "C0603C222K1RACAUTO" FP-C0603C-CF-MFG 2032.24,2405.68 r0 top value="2,200 pF"
C29 "C0603C222K1RACAUTO" FP-C0603C-CF-MFG 1286.42,2450.55 r270 top value="2,200 pF"
C30 "CGA9N3X7R1E476M230KB" FP-CGA9P-IPC_A 209.38,1174.88 r180 top
C31 "GCM155R71C104KA55J" FP-GCM155-0_05-IPC_A 286.77,539.46 r90 top
C32 "GCM155R71C104KA55J" FP-GCM155-0_05-IPC_A 2179,1278.88 r0 top
C33 "C0603C102K4RACAUTO" FP-C0603C-CF-MFG 1589.97,1762.5 r180 top value="1,000 pF"
C34 "ESH477M100AM2AA" FP-ESH477M100AM2AA_RADIAL-MFG 381,3596.88 r270 top value=470µF
C35 "ESH477M100AM2AA" FP-ESH477M100AM2AA_RADIAL-MFG 3259,3601.88 r90 top value=470µF
C36 "CL10C471JB81PNL" FP-CL10-IPC_A 1175.53,662.94 r0 top
C37 "C0603C102K4RACAUTO" FP-C0603C-CF-MFG 2893.1,1166.43 r180 top value="1,000 pF"
C38 "C0603C102K4RACAUTO" FP-C0603C-CF-MFG 2895.58,969.58 r180 top value="1,000 pF"
C39 "C0603C102K4RACAUTO" FP-C0603C-CF-MFG 2892.78,772.73 r180 top value="1,000 pF"
C40 "C0603C102K4RACAUTO" FP-C0603C-CF-MFG 1623,1598.88 r180 top value="1,000 pF"
C41 "C0603C102K4RACAUTO" FP-C0603C-CF-MFG 1537,1567.88 r90 top value="1,000 pF"
C42 "C0603C102K4RACAUTO" FP-C0603C-CF-MFG 1623.18,1536.55 r180 top value="1,000 pF"
C43 "C0603C102K4RACAUTO" FP-C0603C-CF-MFG 1699.83,1447.01 r270 top value="1,000 pF"
C44 "CGA9N3X7S2A106K230KE" 2220_280L 2717.75,2966.88 r180 top value=10uF
C45 "C0603C102K4RACAUTO" FP-C0603C-CF-MFG 1689.8,1762.5 r0 top value="1,000 pF"
C46 "C0603C102K4RACAUTO" FP-C0603C-CF-MFG 1636.87,1447.01 r270 top value="1,000 pF"
C47 "C0603C102K4RACAUTO" FP-C0603C-CF-MFG 1699.83,1352.02 r270 top value="1,000 pF"
C48 "C0603C102K4RACAUTO" FP-C0603C-CF-MFG 1487.93,1763.11 r180 top value="1,000 pF"
C49 "CL10C471JB81PNL" FP-CL10-IPC_A 1175.53,574.88 r0 top
C50 "CL10C471JB81PNL" FP-CL10-IPC_A 1175.53,474.88 r0 top
C51 "GCM155R71C104KA55J" FP-GCM155-0_05-IPC_A 1459.02,2932.91 r270 top
C52 "GCM155R71C104KA55J" FP-GCM155-0_05-IPC_A 1509.51,2931.22 r270 top
C53 "C0603C104K5RACAUTO" 0603L 1146,762.25 r270 top value=0.1uF
C54 "C0603C104K5RACAUTO" 0603L 1146,347.32 r90 top value=0.1uF
C55 "C0603C104K5RACAUTO" 0603L 1146,1102.44 r270 top value=0.1uF
C56 "C0603C104K5RACAUTO" 0603L 1146,989.04 r270 top value=0.1uF
C57 "C0603C104K5RACAUTO" 0603L 1146,875.65 r270 top value=0.1uF
C58 "CGA3E3X7R1E334K080AB" FP-CGA3E3X7R1E334K080AB_0603-MFG 302.51,974.88 r90 top value=330nF
C59 "GCM155R71C104KA55J" FP-GCM155-0_05-IPC_A 301.09,847.32 r90 top
DVDD "5015" Testpoint_Keystone_Miniature 2588.38,1454.88 r180 top
F1 "100VDC 30A" Fuse_0463 693,3191.88 r0 top
FID1 "Fiducial" Fiducial10-20 3197.51,4131.68 r0 top
FID2 "Fiducial" Fiducial10-20 652,4089.88 r0 top
FID3 "Fiducial" Fiducial10-20 3095,139.88 r0 top
GHA "5015" Testpoint_Keystone_Miniature 2756,2492.51 r180 top
GHB "5015" Testpoint_Keystone_Miniature 1734.9,2492.51 r180 top
GHC "5015" Testpoint_Keystone_Miniature 733,2492.51 r0 top
GLA "5015" Testpoint_Keystone_Miniature 3381,2756.88 r90 top
GLB "5015" Testpoint_Keystone_Miniature 2379,2754.89 r90 top
GLC "5015" Testpoint_Keystone_Miniature 1442.25,2742.02 r90 top
GND "D3082-05" Harwin_D3082-05 135.58,2557.44 r90 top
GND1 "D3082-05" Harwin_D3082-05 3533,1879.88 r90 top
GVDD "" LED_LTST-C171 1342.55,92.18 r90 top value=Green
GVDD_EXT "5015" Testpoint_Keystone_Miniature 3266.71,1610.83 r0 top
H1 "1902E" Keystone_1902E 197,4056.88 r0 top
H2 "1902E" Keystone_1902E 3453,4056.88 r0 top
H3 "1902E" Keystone_1902E 3400,224.88 r0 top
H4 "1902E" Keystone_1902E 250,224.88 r0 top
H5 "NY PMS 440 0025 PH" "NY PMS 440 0025 PH" 197,4056.88 r180 bottom
H6 "NY PMS 440 0025 PH" "NY PMS 440 0025 PH" 3453,4056.88 r180 bottom
H7 "NY PMS 440 0025 PH" "NY PMS 440 0025 PH" 3400,224.88 r180 bottom
H8 "NY PMS 440 0025 PH" "NY PMS 440 0025 PH" 250,224.88 r180 bottom
HALL_EXT "5015" Testpoint_Keystone_Miniature 2935.94,354.45 r90 top
J1 "61300311121" WURTH_61300311121 3035.04,1605.21 r90 top
J6 "PBC02SAAN" Sullins_PBC02SAAN 414.27,2426.92 r90 top
J7 "PBC02SAAN" Sullins_PBC02SAAN 143,682.88 r90 top
J8 "SSQ-110-03-G-D" Samtec_SSQ-110-03-x-D 975,824.88 r270 bottom
J9 "SSQ-110-03-G-D" Samtec_SSQ-110-03-x-D 2675,824.88 r270 bottom
J10 "VMOTOR INPUT" Phoenix_1902547 1130.6,3814.93 r180 top
J11 "HALL IN" Phoenix_1792892 3430,966.73 r90 top
J12 "61300311121" WURTH_61300311121 2738,190.88 r0 top
J13 "Motor OUT" Phoenix_1904150 2231.2,3812.93 r180 top
J15 "PBC02SAAN" Sullins_PBC02SAAN 143,943.88 r90 top
L1 "SDR1006-680KL" SDR1006 444.52,1537.39 r270 top value=68uH
Logo1 "CE Mark" CE_Mark_5mm 613,181.44 r180 bottom
Logo2 "Texas Instruments" TI_Stacked_Overlay_Small 1985.39,382.88 r0 top
Logo3 "FCC disclaimer" FCC_disclaimer 2208,2094.88 r180 bottom
Logo4 "WEEE logo" WEEE_Minimum 1279.29,228.4 r180 bottom
LOGO5 "CAUTION HOT SURFACE" IEC_HotSurface_Small 2524.5,3184.38 r180 bottom
LOGO6 "DANGER HIGH VOLTAGE" IEC_HighVoltage_Small 2981,4022.88 r0 top
LOGO7 "CAUTION HOT SURFACE" IEC_HotSurface_Small 1911.93,3299.36 r0 top
LOGO8 "DANGER HIGH VOLTAGE" IEC_HighVoltage_Small 2148,3175.88 r180 bottom
MOTA "5016" Testpoint_Keystone_Compact 3147,3082.07 r0 top
MOTB "5016" Testpoint_Keystone_Compact 2140,3086.88 r0 top
MOTC "5016" Testpoint_Keystone_Compact 1145,3090.88 r0 top
nFAULT "" LED_LTST-C170_Red 1541,93.88 r90 top value=Red
NT1 "Net-Tie" Net-Tie_10mil 3136.46,2227.88 r0 top net-tie
NT2 "Net-Tie" Net-Tie_10mil 2153,2177.88 r90 top net-tie
NT3 "Net-Tie" Net-Tie_10mil 1167,2192.88 r90 top net-tie
NT4 "Net-Tie" Net-Tie_10mil 3084.79,2256.41 r90 top net-tie
NT5 "Net-Tie" Net-Tie_10mil 2064,2219.88 r90 top net-tie
NT6 "Net-Tie" Net-Tie_10mil 1026.99,2321.06 r90 top net-tie
Q1 "SQJ110EP-T1_GE3" PowerPAK_SO-8L 2801.99,2729.89 r180 top value=100V
Q2 "SQJ110EP-T1_GE3" PowerPAK_SO-8L 1796.61,2729.89 r180 top value=100V
Q3 "SQJ110EP-T1_GE3" PowerPAK_SO-8L 809.75,2745.58 r180 top value=100V
Q4 "SQJ110EP-T1_GE3" PowerPAK_SO-8L 3137.49,2707.31 r90 top value=100V
Q5 "SQJ110EP-T1_GE3" PowerPAK_SO-8L 2134,2688.31 r90 top value=100V
Q6 "SQJ110EP-T1_GE3" PowerPAK_SO-8L 1141,2705.31 r90 top value=100V
R4 "CRCW060310K0JNEA" 0603L 2052.61,1134.41 r90 top value=10k
R6 "RCS06030000Z0EA" 0603L 753.44,1302.44 r270 top value=0
R7 "RCS06030000Z0EA" 0603L 1027,1392.88 r90 top value=0
R8 "RCS06030000Z0EA" 0603L 790.66,974.88 r0 top value=0
R9 "RCS06030000Z0EA" 0603L 2110,1282.88 r90 top value=0
R10 "RCS06030000Z0EA" 0603L 2473,474.88 r0 top value=0
R11 "CPF-A-0603B10RE" FP-CPF-A-0603B10RE_0603-MFG 1662.18,1828.84 r0 top value=10
R12 "CRCW0603330RJNEA" 0603L 2071.54,107.51 r90 top value=330
R13 "CRCW06030000Z0EA" 0603L 729,674.88 r270 top value=0
R14 "CRCW0603330RJNEA" 0603L 1635,109.32 r270 top value=330
R15 "CRCW0603330RJNEA" 0603L 1851,110.88 r90 top value=330
R16 "CRCW06034K99FKEA" 0603L 163.29,2105.38 r0 top value=4.99k
R17 "CRCW06034K99FKEA" 0603L 1422,108.88 r90 top value=4.99k
R19 "CRCW06031M00JNEA" 0603L 441.83,2181.41 r0 top value=1.0Meg
R20 "ERJ-2RKF4992X" 0402 186,1636.88 r90 top value=681k
R21 "ERJ-2RKF4533X" 0402 205.83,1911.41 r180 top value=453k
R22 "CRCW0603100KFKEA" 0603L 2876.97,2505.87 r90 top value=100k
R23 "CRCW0402100KFKED" 0402L 350,2181.88 r0 top value=100k
R24 "ERJ-2RKF4992X" 0402 283.8,1938.41 r270 top value=49.9k
R25 "2.7" RESC1608X55X30LL20T10 2737.01,3230.15 r180 top
R26 "2.7" RESC1608X55X30LL20T10 2461.1,3238.06 r0 top
R27 "2.7" RESC1608X55X30LL20T10 1609.51,3276.09 r0 top
R28 "RCS06030000Z0EA" 0603L 2756,2375.88 r0 top value=0
R29 "RCS06030000Z0EA" 0603L 1718,2393.94 r0 top value=0
R30 "RCS06030000Z0EA" 0603L 955.92,2367.56 r90 top value=0
R31 "CRE2512-FZ-R005E-3" CRE2512-R5_R9 3251,2372.61 r90 top value=0.005
R32 "CPF-A-0603B10RE" FP-CPF-A-0603B10RE_0603-MFG 1444,1598.88 r180 top value=10
R33 "CRE2512-FZ-R005E-3" CRE2512-R5_R9 2214,2358.88 r90 top value=0.005
R34 "RCS06030000Z0EA" 0603L 3021.28,2256.88 r90 top value=0
R35 "RCS06030000Z0EA" 0603L 1980.44,2216.45 r90 top value=0
R36 "RCS06030000Z0EA" 0603L 1429.35,2480.03 r180 top value=0
R37 "RCS06030000Z0EA" 0603L 3010,2510.88 r90 top value=0
R38 "RCS06030000Z0EA" 0603L 2008,2503.88 r90 top value=0
R39 "RCS06030000Z0EA" 0603L 2276,1618.88 r0 top value=0
R40 "2.7" RESC1608X55X30LL20T10 2736,3343.09 r0 top
R41 "2.7" RESC1608X55X30LL20T10 2457.81,3347.68 r180 top
R42 "2.7" RESC1608X55X30LL20T10 1607.31,3373.78 r180 top
R43 "CRCW12060000Z0EAC" FP-CRCW12060000Z0EAC_1206-MFG 2660.66,2277.93 r180 top value=0
R44 "CRCW12060000Z0EAC" FP-CRCW12060000Z0EAC_1206-MFG 1656.16,2277.93 r180 top value=0
R45 "CPF-A-0603B10RE" FP-CPF-A-0603B10RE_0603-MFG 1521.44,1828.84 r0 top value=10
R46 "CRCW060310K0JNEA" 0603L 2920.34,859.55 r270 top value=10k
R47 "CRCW060310K0JNEA" 0603L 2923.14,1056.4 r270 top value=10k
R48 "CRCW060310K0JNEA" 0603L 2920.34,1253.25 r270 top value=10k
R49 "160" RESC1608X55X30ML15T15 1298.56,574.88 r0 top
R50 "CPF-A-0603B10RE" FP-CPF-A-0603B10RE_0603-MFG 1558.88,1426.57 r270 top value=10
R51 "CRE2512-FZ-R005E-3" CRE2512-R5_R9 1158,2370.88 r90 top value=0.005
R52 "CRCW060397K6FKEA" 0603L 1909.39,1828.84 r270 top value=97.6k
R53 "CPF-A-0603B10RE" FP-CPF-A-0603B10RE_0603-MFG 1636.32,1337.55 r270 top value=10
R54 "CPF-A-0603B10RE" FP-CPF-A-0603B10RE_0603-MFG 1449.56,1517.16 r180 top value=10
R55 "CRCW060397K6FKEA" 0603L 1407,1802.88 r270 top value=97.6k
R56 "RCS06030000Z0EA" 0603L 1013,2479.88 r90 top value=0
R57 "CRCW0603330KJNEA" 0603L 357,2280.88 r0 top value=330k
R58 "CRCW06030000Z0EA" 0603L 664,457.88 r270 top value=0
R59 "160" RESC1608X55X30ML15T15 1297.78,662.94 r0 top
R60 "CRCW0603100KFKEA" 0603L 1878,2502.88 r90 top value=100k
R63 "160" RESC1608X55X30ML15T15 1297.78,474.88 r0 top
R65 "CRCW060397K6FKEA" 0603L 419.27,2537.29 r180 top value=97.6k
R66 "CRCW06033K01FKEA" 0603L 548.68,2534.88 r180 top value=3.01k
R74 "CRCW060397K6FKEA" 0603L 2279.19,1694.64 r90 top value=97.6k
R75 "CRCW0603100KFKEA" 0603L 957,2479.88 r90 top value=100k
R76 "CRCW0603100KFKEA" 0603L 3047,2345.88 r0 top value=100k
R77 "CRCW0603100KFKEA" 0603L 2030.06,2314.01 r0 top value=100k
R78 "CRCW0603100KFKEA" 0603L 1354.19,2450.55 r270 top value=100k
R80 "CRCW06033K01FKEA" 0603L 2335.55,1695.05 r270 top value=3.01k
R81 "CRCW06033K01FKEA" 0603L 1851.37,1828.84 r90 top value=3.01k
R82 "CRCW06033K01FKEA" 0603L 1354.19,1802.93 r90 top value=3.01k
R86 "CRCW060397K6FKEA" 0603L 1268.33,346.86 r270 top value=97.6k
R91 "CRCW06033K01FKEA" 0603L 1208.09,346.86 r90 top value=3.01k
SH-J1 "SNT-100-BK-G" SNT-100-BK-G 4239,67.88 r270 top value=1x2
SH-J2 "SNT-100-BK-G" SNT-100-BK-G 4117,403.88 r270 top value=1x2
SH-J3 "SNT-100-BK-G" SNT-100-BK-G 3976,69.88 r90 top value=1x2
SH-J4 "SNT-100-BK-G" SNT-100-BK-G 3751,69.88 r90 top value=1x2
SH-J5 "SNT-100-BK-G" SNT-100-BK-G 3822,408.88 r90 top value=1x2
SLA "5015" Testpoint_Keystone_Miniature 3429.63,2310.18 r90 top
SLB "5015" Testpoint_Keystone_Miniature 2379,2274.88 r90 top
SLC "5015" Testpoint_Keystone_Miniature 1367.45,2283.97 r90 top
TP_3.3V "5015" Testpoint_Keystone_Miniature 1000.26,1682.3 r0 top
TP_5V "5015" Testpoint_Keystone_Miniature 994.49,1501.72 r0 top
U1 "DRV8363RGZRQ1" RGZ0048L-MFG 2009.08,1493.62 r0 top
U2 "LM5164DDAT" DDA0008E_N 443.83,2013.41 r270 top
U3 "UA78M33CDCYR" DCY0004A_N 504.48,603.37 r0 top
U4 "TPD4S009DRYR" DRY0006A 1464,347.26 r0 top
U5 "TPD4S009DRYR" DRY0006A 1354,907.88 r0 top
U6 "TMP235A2DBZR" DBZ0003A-MFG 1472.51,3052.16 r90 top
U7 "UA78M05CDCYR" DCY0004A_N 504.48,922.41 r0 top
VMOTOR "5016" Testpoint_Keystone_Compact 414.27,2745.58 r90 top
VMOTOR_LED "Green" LED_LTST-C171 149.51,2197.41 r0 top
VREF_EXT "5015" Testpoint_Keystone_Miniature 2194.64,1070.55 r180 top
ZZ1 "This Assembly Note is for PCB labels only" AssemblyNoteLabel 4947.75,2161.34 r90 top
ZZ2 "These assemblies are ESD sensitive, ESD precautions shall be observed." AssemblyNote 4770.59,4641.65 r90 top
ZZ3 "These assemblies must be clean and free from flux and all contaminants. Use of no clean flux is not acceptable." AssemblyNote 4593.42,3096.38 r90 top
ZZ4 "These assemblies must comply with workmanship standards IPC-A-610 Class 2, unless otherwise specified." AssemblyNote 4416.26,3421.18 r90 top

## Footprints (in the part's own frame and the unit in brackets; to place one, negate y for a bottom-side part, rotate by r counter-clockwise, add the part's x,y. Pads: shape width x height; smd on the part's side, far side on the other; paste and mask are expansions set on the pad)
0402 [mm] "0402 from SM-752 data"
  rect 0.8x0.6 smd: 1(-0.6,0) 2(0.6,0)
  silkscreen extent -1.22,-0.52 1.22,0.52, body extent -0.55,-0.3 0.55,0.3, height 0.6
0402L [mm] "0402 from SM-752 data"
  rect 0.6x0.5 smd: 1(-0.5,0) 2(0.5,0)
  body extent -0.55,-0.3 0.55,0.3, height 0.6
0603L [mm] "0603 from SM-752 data"
  rect 0.8x0.85 smd: 1(-0.7,0) 2(0.7,0)
  silkscreen extent -0.07,-0.33 0.07,0.33, body extent -0.87,-0.47 0.87,0.47, height 1
2220_280L [mm] "Chip Capacitor, Body 5.7x5.0mm, IPC High Density"
  rect 1.4x5.2 smd: 1(-2.5,0) 2(2.5,0)
  silkscreen extent -1.4,-2.5 1.4,2.5, body extent -2.95,-2.6 2.95,2.65, height 2.8
AssemblyNote [mil] "Assembly Note"
AssemblyNoteLabel [mil] "Assembly Note for PCB Labels"
CE_Mark_5mm [mil] "Minimum text height for CE Mark"
  silkscreen extent -138,-98 138,98
CRE2512-R5_R9 [mm] "SMD, 2-Leads, Body 6.45x3.35mm, Pitch 6.2mm"
  rect 2.1x4 smd: 1(-3.1,0) 2(3.1,0)
  silkscreen extent -1.6,-1.78 1.6,1.78, body extent -3.32,-1.77 3.32,1.77, height 0.9
DBZ0003A-MFG [mm]
  rrect17% 1.3x0.6 smd paste+0 mask+0: 1(-1.05,0.95) 2(-1.05,-0.95) 3(1.05,0)
  silkscreen extent -0.7,-1.52 0.7,1.52, body extent -1.8,-1.62 1.8,1.62, height 0.25
DCY0004A_N [mm] "SOT223/SC73, 4-Leads, Body 6.5x3.5mm, Pitch 2.3mm, Lead Span 7mm, IPC Medium Density"
  rrect11% 1.75x0.9 smd: 1(-3.125,2.3) 2(-3.125,0) 3(-3.125,-2.3)
  rrect6% 1.75x3.2 smd: 4(3.125,0)
  silkscreen extent -3.02,-3.35 1.4,3.47, body extent -3.48,-3.25 3.48,3.25, height 1.68
DDA0008E_N [mm]
  rrect17% 1.45x0.6 smd: 1(-2.725,1.905) 2(-2.725,0.635) 3(-2.725,-0.635) 4(-2.725,-1.905) 5(2.725,-1.905) 6(2.725,-0.635) 7(2.725,0.635) 8(2.725,1.905)
  rrect4% 2.4x3.1 on Top Paste: 9(0,0)
  rrect7% 2.95x4.9 smd paste-1.5 mask-1.5: 9(0,0)
  rrect4% 2.4x3.1 on Top Solder: 9(0,0)
  silkscreen extent -3.22,-2.5 1.4,2.5, body extent -3,-2.45 3,2.45, height 1.57
DRY0006A [mm] "USON-6"
  rrect67% 0.45x0.3 smd paste-0.05 mask-0.05: 1(-0.275,0.5)
  rrect67% 0.4x0.3 smd paste-0.05 mask-0.05: 2(-0.3,0) 3(-0.3,-0.5) 4(0.3,-0.5) 5(0.3,0) 6(0.3,0.5)
  body extent -0.5,-0.72 0.5,0.73, height 0.58
FCC_disclaimer [mil]
Fiducial10-20 [mm]
  round 1 smd mask+0.5: 1(0,0)
  Top Layer keep-out circle w1.178: c0,0 r0.5
FP-C0603C-CF-MFG [mm]
  rect 0.75x0.9 smd paste+0 mask+0: 1(-0.6,0) 2(0.6,0)
  silkscreen extent -0.87,-0.85 0.88,0.85, body extent -1.2,-0.6 1.2,0.6, height 0.25
FP-C1210C225K1RACAUTO-MFG [mm]
  rect 0.95x2.6 smd paste+0 mask+0: 1(-1.4,0) 2(1.4,0)
  silkscreen extent -0.55,-1.35 0.55,1.35, body extent -2,-1.45 2,1.45, height 0.25
FP-CGA3E3X7R1E334K080AB_0603-MFG [mm]
  rrect14% 0.7x0.7 smd paste+0 mask+0: 1(-0.7,0) 2(0.7,0)
  silkscreen extent -0.95,-0.72 0.95,0.72, body extent -1.15,-0.65 1.15,0.65, height 0.25
FP-CGA9P-IPC_A [mm]
  rect 1.153x5.503 smd paste+0 mask+0: 1(-3.025,0) 2(3.025,0)
  silkscreen extent -2.15,-2.75 2.15,2.75, body extent -4.1,-3.25 4.1,3.25, height 0.25
FP-CL10-IPC_A [mil]
  rect 45.6x39.85 smd paste+0 mask+0: 1(-32.56,0) 2(32.56,0)
  silkscreen extent -55,-36 55,36, body extent -75,-40 75,40, height 10
FP-CPF-A-0603B10RE_0603-MFG [mm]
  rrect11% 1x0.9 smd paste+0 mask+0: 1(-0.9,0) 2(0.9,0)
  silkscreen extent 0,-0.45 0,0.45, body extent -1.5,-0.55 1.5,0.55, height 0.25
FP-CRCW12060000Z0EAC_1206-MFG [mm]
  rrect11% 0.9x1.7 smd paste+0 mask+0: 1(-1.45,0) 2(1.45,0)
  silkscreen extent -0.63,-0.82 0.63,0.82, body extent -2,-0.95 2,0.95, height 0.25
FP-ESH477M100AM2AA_RADIAL-MFG [mm]
  rrect7% 1.45x1.45 hole 0.95 paste-1000 mask+0: 1(-3.75,0)
  round 1.45 hole 0.95 paste-1000 mask+0: 2(3.75,0)
  silkscreen extent -8.25,-8.25 8.25,8.25, body extent -8.35,-8.35 8.35,8.35, height 0.25
FP-GCM155-0_05-IPC_A [mil]
  rect 28.16x26.48 smd paste+0 mask+0: 1(-18.84,0) 2(18.84,0)
  silkscreen extent -33,-29 33,29, body extent -41,-21 41,21, height 10
FP-GCM155-0_05-IPC_B [mil]
  rect 24.23x22.54 smd paste+0 mask+0: 1(-16.87,0) 2(16.87,0)
  silkscreen extent -29,-27 29,27, body extent -35,-17 35,17, height 10
FP-GRT21B-0_2-IPC_B [mil]
  rect 49.4x57.33 smd paste+0 mask+0: 1(-32.51,0) 2(32.51,0)
  silkscreen extent -57,-44 57,44, body extent -67,-39 67,39, height 10
FP-GRT155-0_2-IPC_A [mil]
  rect 32.6x31.74 smd paste+0 mask+0: 1(-19.25,0) 2(19.25,0)
  silkscreen extent -36,-32 36,32, body extent -43,-24 43,24, height 10
FP-GRT188-0_1-e0_2_0_5-IPC_B [mil]
  rect 37.74x35.91 smd paste+0 mask+0: 1(-28.61,0) 2(28.61,0)
  silkscreen extent -47,-34 47,34, body extent -57,-28 57,28, height 10
FP-GRT188-0_1-e0_2_0_5-IPC_C [mil]
  rect 29.87x31.97 smd paste+0 mask+0: 1(-24.67,0) 2(24.67,0)
  silkscreen extent -40,-33 40,33, body extent -44,-22 44,22, height 10
Fuse_0463 [mm] "SMD, 2-Leads, Body 10.1x3.12mm"
  rrect3% 3.25x3.43 smd: 1(-4.675,0) 2(4.675,0)
  silkscreen extent -2.6,-1.5 2.6,1.5, body extent -5.05,-1.56 5.05,1.56, height 3.12
Harwin_D3082-05 [mm] "Shorting Plug, 10.16mm spacing, TH"
  round 1.8 hole 1.3: 1(-5.08,0) 2(5.08,0)
  silkscreen extent -3.9,-0.53 3.9,0.53, body extent -5.6,-0.52 5.61,0.52, height 6.63
IEC_HighVoltage_Small [mil]
  silkscreen extent -107,-88 107,97
IEC_HotSurface_Small [mil]
  silkscreen extent -107,-93 107,92
Keystone_1902E [mil] "Hex Standoff, 4-40 threaded, nylon"
  round 1 on Mech3: 0(0,0)
  body extent -145,-126 146,126, height 1001
LED_LTST-C170_Red [mm] "LITE-ON"
  rect 1.2x1.2 smd: 1(-1.05,0) 2(1.05,0)
  silkscreen extent -1.6,-1 2.2,1, body extent -1.05,-0.67 1.05,0.67, height 1.1
LED_LTST-C171 [mm] "LITE-ON"
  rect 1.2x1.2 smd: 1(-1.05,0) 2(1.05,0)
  silkscreen extent -1.6,-1 2.2,1, body extent -1.05,-0.67 1.05,0.67, height 0.8
Net-Tie_10mil [mil] "10mil net tie, no solder mask opening, no solder paste"
  rect 10x10 smd paste-5 mask-5: 1(-10,0) 2(10,0)
  Top Layer region: -6,5 6,5 6,-5 -6,-5
"NY PMS 440 0025 PH" [mm] "4-40 nylon screw and mounting hole"
  round 8 hole 3.2: 1(0,0)
  body extent -3.31,-3.3 3.3,3.3, height 2.69
Phoenix_1792892 [mm] "Terminal Block, 5mm, 5x1, R/A, TH"
  rrect50% 1.7x1.7 hole 1.2: 1(-10,0)
  round 1.7 hole 1.2: 2(-5,0) 3(0,0) 4(5,0) 5(10,0)
  silkscreen extent -12.8,-4.95 12.5,5.55, body extent -12.5,-4.95 12.5,5.55, height 13.6
Phoenix_1902547 [mm] "TH, 2-Leads, Body 19.04x16mm, Pitch 9.52mm"
  rect 1.8x1.8 hole 1.3: 1(-4.76,3.1)
  round 1.8 hole 1.3: 2(4.76,3.1)
  silkscreen extent -10,-8 10.09,8, body extent -9.52,-8 10.09,8, height 22
Phoenix_1904150 [mm] "TH, 3-Leads, Body 28.56x16mm, Pitch 9.52mm"
  rect 1.8x1.8 hole 1.3: 1(-9.52,3.1)
  round 1.8 hole 1.3: 2(0,3.1) 3(9.52,3.1)
  silkscreen extent -14.8,-8 14.85,8, body extent -14.28,-8 14.85,8, height 22
PowerPAK_SO-8L [mm] "based on Vishay recommended land pattern Document 63818 Feb 7, 2012"
  rect 1x0.41 smd: 1(-2.805,1.905) 2(-2.805,0.635) 3(-2.805,-0.635) 4(-2.805,-1.905)
  rect 3.63x4.061 smd: 5(0.805,0)
  Top Layer region: -0.297,-2.64 0.298,-2.64 0.298,-2.03 -0.297,-2.03
  Top Layer region: 2.615,-2.5 3.125,-2.5 3.125,2.5 2.615,2.5
  Top Layer region: -0.298,2.03 0.297,2.03 0.297,2.64 -0.298,2.64
  body extent -3.07,-2.57 3.08,2.57, height 1.21
RESC1608X55X30LL20T10 [mm] "Chip Resistor, 2-Leads, Body 1.60x0.80mm, IPC High Density"
  rect 0.7x0.9 smd: 1(-0.65,0) 2(0.65,0)
  body extent -0.9,-0.5 0.9,0.5, height 0.55
RESC1608X55X30ML15T15 [mm] "Chip Resistor, 2-Leads, Body 1.60x0.80mm, IPC Low Density"
  rect 0.9x1.05 smd: 1(-0.725,0) 2(0.725,0)
  body extent -0.87,-0.48 0.87,0.48, height 0.55
RGZ0048L-MFG [mm]
  rrect42% 0.6x0.24 smd paste+0 mask+0: 1(-3.4,2.75) 2(-3.4,2.25) 3(-3.4,1.75) 4(-3.4,1.25) 5(-3.4,0.75) 6(-3.4,0.25) 7(-3.4,-0.25) 8(-3.4,-0.75) 9(-3.4,-1.25) 10(-3.4,-1.75) 11(-3.4,-2.25) 12(-3.4,-2.75) 25(3.4,-2.75) 26(3.4,-2.25) 27(3.4,-1.75) 28(3.4,-1.25) 29(3.4,-0.75) 30(3.4,-0.25) 31(3.4,0.25) 32(3.4,0.75) 33(3.4,1.25) 34(3.4,1.75) 35(3.4,2.25) 36(3.4,2.75)
  rrect42% 0.24x0.6 smd paste+0 mask+0: 13(-2.75,-3.4) 14(-2.25,-3.4) 15(-1.75,-3.4) 16(-1.25,-3.4) 17(-0.75,-3.4) 18(-0.25,-3.4) 19(0.25,-3.4) 20(0.75,-3.4) 21(1.25,-3.4) 22(1.75,-3.4) 23(2.25,-3.4) 24(2.75,-3.4) 37(2.75,3.4) 38(2.25,3.4) 39(1.75,3.4) 40(1.25,3.4) 41(0.75,3.4) 42(0.25,3.4) 43(-0.25,3.4) 44(-0.75,3.4) 45(-1.25,3.4) 46(-1.75,3.4) 47(-2.25,3.4) 48(-2.75,3.4)
  rrect2% 4.6x4.975 smd paste-1000 mask+0: 49(0,-0.188)
  silkscreen extent -4.4,-3.55 3.55,3.55, body extent -3.8,-3.8 3.8,3.8, height 0.25
Samtec_SSQ-110-03-x-D [mm] "Receptacle, 2.54mm, 10x2, TH"
  rect 1.55x1.55 hole 1.02: 1(-11.43,1.27)
  round 1.55 hole 1.02: 2(-11.43,-1.27) 3(-8.89,1.27) 4(-8.89,-1.27) 5(-6.35,1.27) 6(-6.35,-1.27) 7(-3.81,1.27) 8(-3.81,-1.27) 9(-1.27,1.27) 10(-1.27,-1.27) 11(1.27,1.27) 12(1.27,-1.27) 13(3.81,1.27) 14(3.81,-1.27) 15(6.35,1.27) 16(6.35,-1.27) 17(8.89,1.27) 18(8.89,-1.27) 19(11.43,1.27) 20(11.43,-1.27)
  silkscreen extent -12.95,-2.48 12.95,3, body extent -12.95,-2.48 12.95,2.48, height 8.51
SDR1006 [mm] "Bourns recommended land pattern"
  oval 3.6x10 smd: 1(-3.2,0) 2(3.2,0)
  rect 2x2 smd: 1(-2.4,4) 1(-2.4,-4) 2(2.4,4) 2(2.4,-4)
  silkscreen extent -5.4,-5.43 5.4,5.43, body extent -4.9,-4.9 4.86,4.88, height 5.8
SNT-100-BK-G [mil] "Samtec STEP model"
  round 1 on Mech3: 0(0,0)
  body extent -100,-50 100,50, height 344
Sullins_PBC02SAAN [mm] "Sullins 100mil, 1x2, 230 mil above insulator"
  rect 1.65x1.65 hole 1.016: 1(0,1.27)
  round 1.65 hole 1.016: 2(0,-1.27)
  silkscreen extent -1.37,-2.54 1.27,3.1, body extent -1.27,-2.54 1.27,2.54, height 8.38
Testpoint_Keystone_Compact [mil] "Compact SMT test point"
  rect 185x135 smd: 1(0,0)
  silkscreen extent -110,-80 110,80, body extent -75,-56 75,56, height 91
Testpoint_Keystone_Miniature [mil] "Miniature SMT test point"
  rect 135x70 smd: 1(0,0)
  silkscreen extent -78,-46 78,45, body extent -52,-20 52,20, height 61
TI_Stacked_Overlay_Small [mil]
  silkscreen extent -418,-98 418,98
WEEE_Minimum [mil] "WEEElie bin"
  silkscreen extent -95,-172 99,104
WURTH_61300311121 [mm] "Header, 2.54mm, 3x1, TH"
  rrect50% 1.65x1.65 hole 1.15: 1(-2.54,0)
  round 1.65 hole 1.15: 2(0,0) 3(2.54,0)
  body extent -3.81,-1.27 3.81,1.27, height 8.54

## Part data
3.3V 5V GVDD VMOTOR_LED: library part CMP-0002830-3, "LED, Green, SMD", Color=green, Manufacturer=Lite-On, PartNumber=LTST-C171GKT, Value1=W, Value2=2.1V
3.3V_EXT 5V_EXT BUCK_EXT BUCK_TP DVDD GHA GHB GHC GLA GLB GLC GVDD_EXT HALL_EXT SLA SLB SLC TP_3.3V TP_5V VREF_EXT: library part CMP-0055152-2, "Test Point, Miniature, SMT", Manufacturer="Keystone Electronics", Supplier Part Number 1=36-5015TR-ND
C1 C3 C4 C6 C7 C8: library part CMP-06035-050353-1, "Multi-Layer Ceramic Capacitor 1uF 25V X7R ±10% 0603 Paper T/R GRT188R71E105KE13D"
C5: library part CMP-06035-008164-1, "Multi-Layer Ceramic Capacitor 10uF 25V X7S ±10% 0805 Emboss T/R GRT21BC71E106KE13L"
C9: library part CMP-06035-019999-1, "Multi-Layer Ceramic Capacitor 2.2uF 16V X5R ±10% 0402 Paper T/R GRT155R61C225KE13J"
